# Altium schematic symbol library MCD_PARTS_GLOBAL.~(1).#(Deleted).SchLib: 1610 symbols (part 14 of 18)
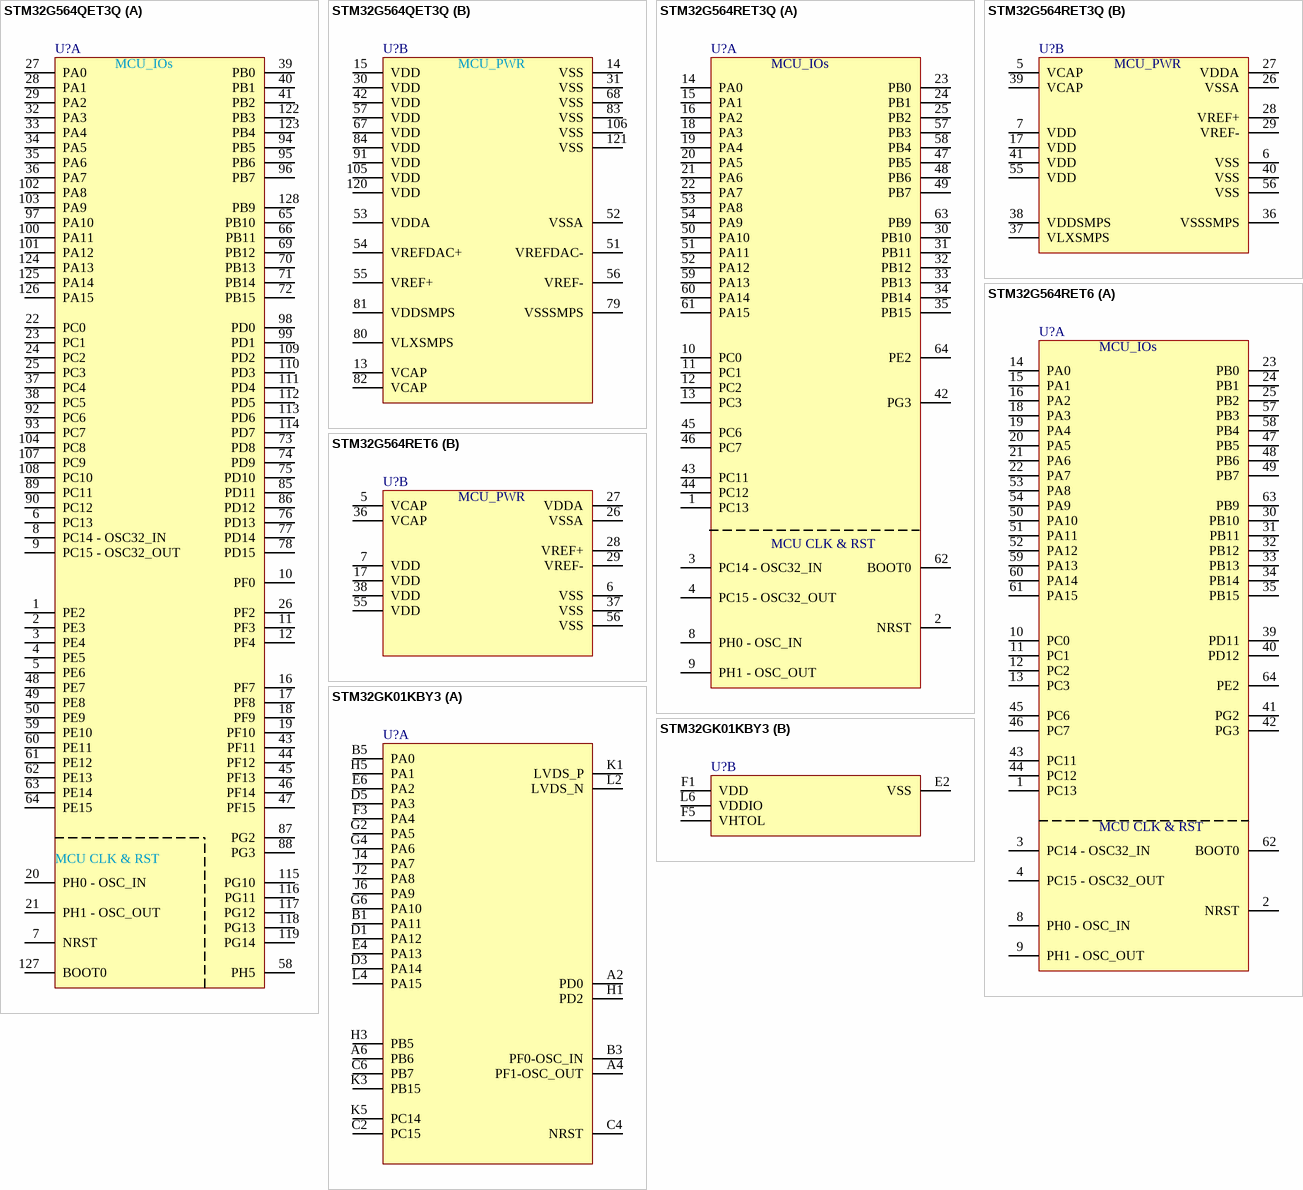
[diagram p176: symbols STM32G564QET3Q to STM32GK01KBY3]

## STM32G564QET3Q
designator U?
part A pins: 1 PE2, 2 PE3, 3 PE4, 4 PE5, 5 PE6, 6 PC13, 7 NRST, 8 PC14 - OSC32_IN, 9 PC15 - OSC32_OUT, 10 PF0, 11 PF3, 12 PF4, 16 PF7, 17 PF8, 18 PF9, 19 PF10, 20 PH0 - OSC_IN, 21 PH1 - OSC_OUT, 22 PC0, 23 PC1, 24 PC2, 25 PC3, 26 PF2, 27 PA0, 28 PA1, 29 PA2, 32 PA3, 33 PA4, 34 PA5, 35 PA6, 36 PA7, 37 PC4, 38 PC5, 39 PB0, 40 PB1, 41 PB2, 43 PF11, 44 PF12, 45 PF13, 46 PF14, 47 PF15, 48 PE7, 49 PE8, 50 PE9, 58 PH5, 59 PE10, 60 PE11, 61 PE12, 62 PE13, 63 PE14, 64 PE15, 65 PB10, 66 PB11, 69 PB12, 70 PB13, 71 PB14, 72 PB15, 73 PD8, 74 PD9, 75 PD10, 76 PD13, 77 PD14, 78 PD15, 85 PD11, 86 PD12, 87 PG2, 88 PG3, 89 PC11, 90 PC12, 92 PC6, 93 PC7, 94 PB5, 95 PB6, 96 PB7, 97 PA10, 98 PD0, 99 PD1, 100 PA11, 101 PA12, 102 PA8, 103 PA9, 104 PC8, 107 PC9, 108 PC10, 109 PD2, 110 PD3, 111 PD4, 112 PD5, 113 PD6, 114 PD7, 115 PG10, 116 PG11, 117 PG12, 118 PG13, 119 PG14, 122 PB3, 123 PB4, 124 PA13, 125 PA14, 126 PA15, 127 BOOT0, 128 PB9
part B pins: 13 VCAP, 14 VSS, 15 VDD, 30 VDD, 31 VSS, 42 VDD, 51 VREFDAC-, 52 VSSA, 53 VDDA, 54 VREFDAC+, 55 VREF+, 56 VREF-, 57 VDD, 67 VDD, 68 VSS, 79 VSSSMPS, 80 VLXSMPS, 81 VDDSMPS, 82 VCAP, 83 VSS, 84 VDD, 91 VDD, 105 VDD, 106 VSS, 120 VDD, 121 VSS

## STM32G564RET3Q
designator U?
part A pins: 1 PC13, 2 NRST, 3 PC14 - OSC32_IN, 4 PC15 - OSC32_OUT, 8 PH0 - OSC_IN, 9 PH1 - OSC_OUT, 10 PC0, 11 PC1, 12 PC2, 13 PC3, 14 PA0, 15 PA1, 16 PA2, 18 PA3, 19 PA4, 20 PA5, 21 PA6, 22 PA7, 23 PB0, 24 PB1, 25 PB2, 30 PB10, 31 PB11, 32 PB12, 33 PB13, 34 PB14, 35 PB15, 42 PG3, 43 PC11, 44 PC12, 45 PC6, 46 PC7, 47 PB5, 48 PB6, 49 PB7, 50 PA10, 51 PA11, 52 PA12, 53 PA8, 54 PA9, 57 PB3, 58 PB4, 59 PA13, 60 PA14, 61 PA15, 62 BOOT0, 63 PB9, 64 PE2
part B pins: 5 VCAP, 6 VSS, 7 VDD, 17 VDD, 26 VSSA, 27 VDDA, 28 VREF+, 29 VREF-, 36 VSSSMPS, 37 VLXSMPS, 38 VDDSMPS, 39 VCAP, 40 VSS, 41 VDD, 55 VDD, 56 VSS

## STM32G564RET6
designator U?
part A pins: 1 PC13, 2 NRST, 3 PC14 - OSC32_IN, 4 PC15 - OSC32_OUT, 8 PH0 - OSC_IN, 9 PH1 - OSC_OUT, 10 PC0, 11 PC1, 12 PC2, 13 PC3, 14 PA0, 15 PA1, 16 PA2, 18 PA3, 19 PA4, 20 PA5, 21 PA6, 22 PA7, 23 PB0, 24 PB1, 25 PB2, 30 PB10, 31 PB11, 32 PB12, 33 PB13, 34 PB14, 35 PB15, 39 PD11, 40 PD12, 41 PG2, 42 PG3, 43 PC11, 44 PC12, 45 PC6, 46 PC7, 47 PB5, 48 PB6, 49 PB7, 50 PA10, 51 PA11, 52 PA12, 53 PA8, 54 PA9, 57 PB3, 58 PB4, 59 PA13, 60 PA14, 61 PA15, 62 BOOT0, 63 PB9, 64 PE2
part B pins: 5 VCAP, 6 VSS, 7 VDD, 17 VDD, 26 VSSA, 27 VDDA, 28 VREF+, 29 VREF-, 36 VCAP, 37 VSS, 38 VDD, 55 VDD, 56 VSS

## STM32GK01KBY3
designator U?
part A pins: A2 PD0, A4 PF1-OSC_OUT, A6 PB6, B1 PA11, B3 PF0-OSC_IN, B5 PA0, C2 PC15, C4 NRST, C6 PB7, D1 PA12, D3 PA14, D5 PA3, E4 PA13, E6 PA2, F3 PA4, G2 PA5, G4 PA6, G6 PA10, H1 PD2, H3 PB5, H5 PA1, J2 PA8, J4 PA7, J6 PA9, K1 LVDS_P, K3 PB15, K5 PC14, L2 LVDS_N, L4 PA15
part B pins: E2 VSS, F1 VDD (power), F5 VHTOL (power), L6 VDDIO (power)

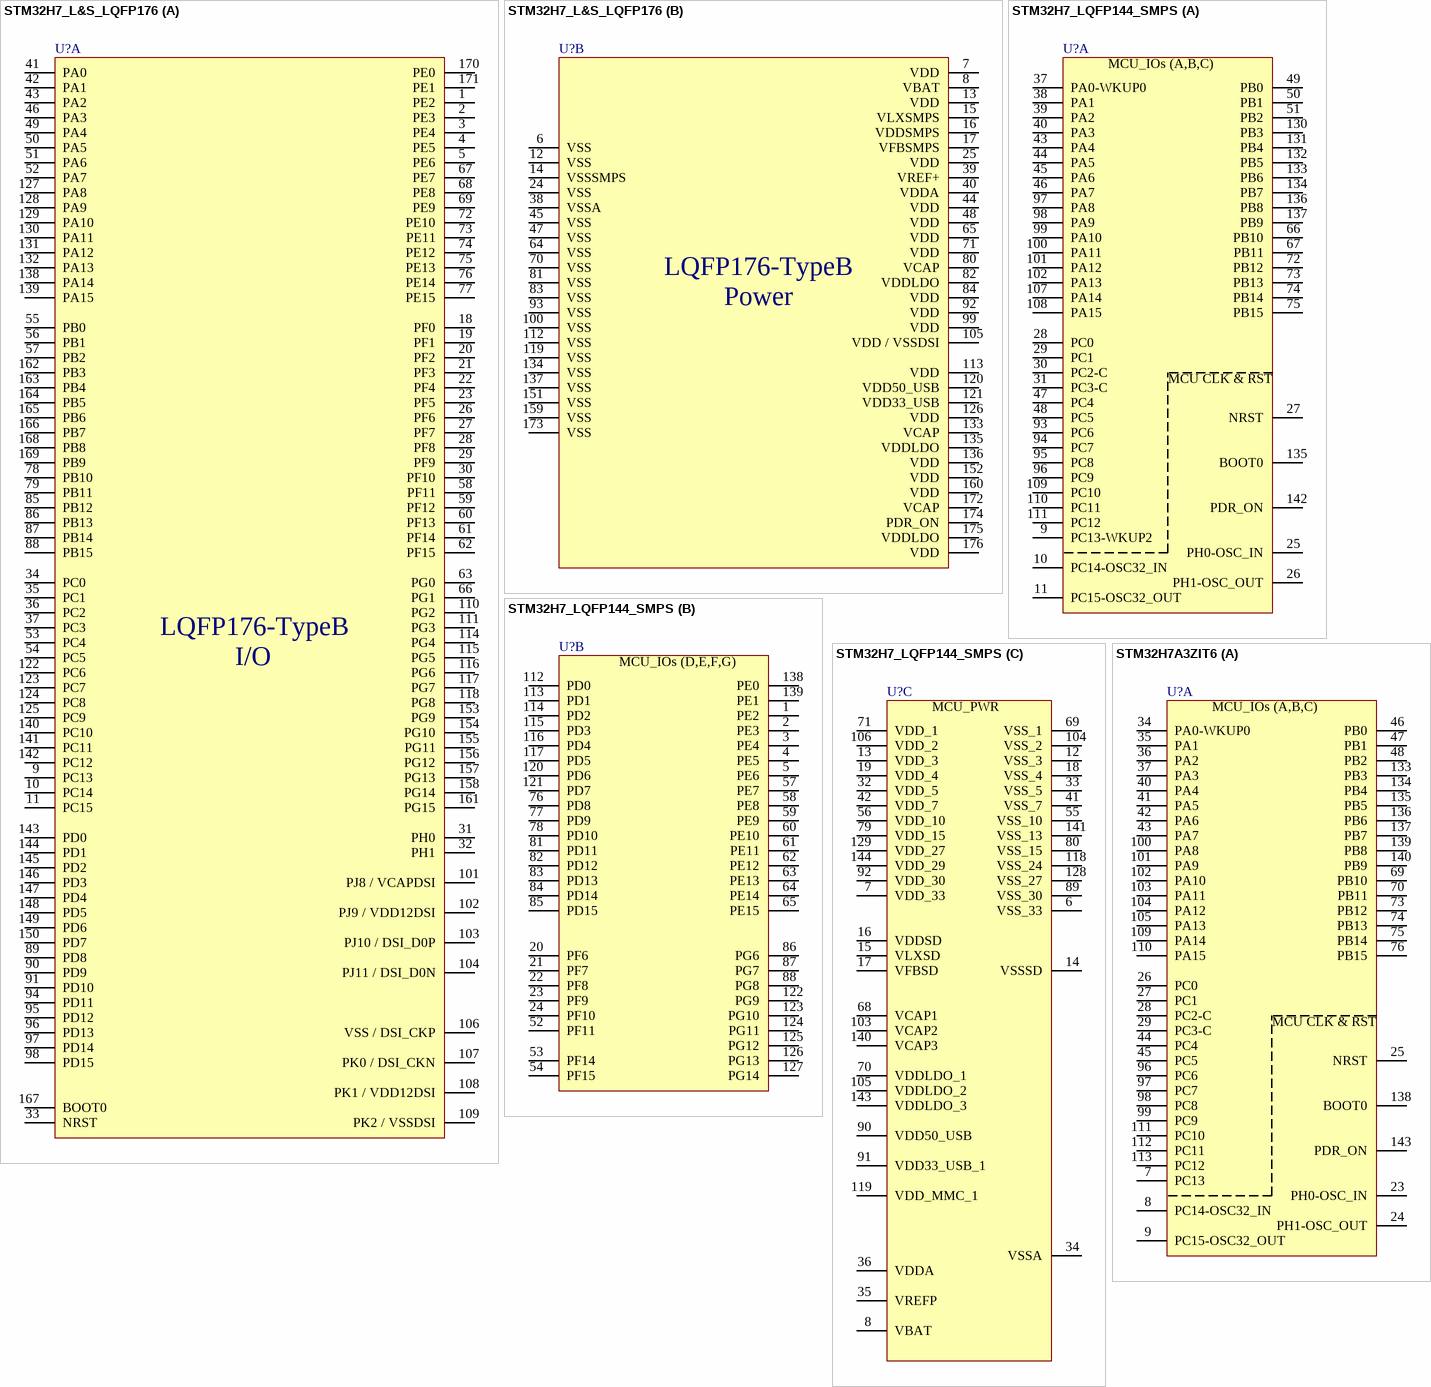
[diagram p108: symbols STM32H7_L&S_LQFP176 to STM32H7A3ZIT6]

## STM32H7_L&S_LQFP176
designator U?
part A pins: 1 PE2, 2 PE3, 3 PE4, 4 PE5, 5 PE6, 9 PC13, 10 PC14, 11 PC15, 18 PF0, 19 PF1, 20 PF2, 21 PF3, 22 PF4, 23 PF5, 26 PF6, 27 PF7, 28 PF8, 29 PF9, 30 PF10, 31 PH0, 32 PH1, 33 NRST, 34 PC0, 35 PC1, 36 PC2, 37 PC3, 41 PA0, 42 PA1, 43 PA2, 46 PA3, 49 PA4, 50 PA5, 51 PA6, 52 PA7, 53 PC4, 54 PC5, 55 PB0, 56 PB1, 57 PB2, 58 PF11, 59 PF12, 60 PF13, 61 PF14, 62 PF15, 63 PG0, 66 PG1, 67 PE7, 68 PE8, 69 PE9, 72 PE10, 73 PE11, 74 PE12, 75 PE13, 76 PE14, 77 PE15, 78 PB10, 79 PB11, 85 PB12, 86 PB13, 87 PB14, 88 PB15, 89 PD8, 90 PD9, 91 PD10, 94 PD11, 95 PD12, 96 PD13, 97 PD14, 98 PD15, 101 PJ8 / VCAPDSI, 102 PJ9 / VDD12DSI, 103 PJ10 / DSI_D0P, 104 PJ11 / DSI_D0N, 106 VSS / DSI_CKP, 107 PK0 / DSI_CKN, 108 PK1 / VDD12DSI, 109 PK2 / VSSDSI, 110 PG2, 111 PG3, 114 PG4, 115 PG5, 116 PG6, 117 PG7, 118 PG8, 122 PC6, 123 PC7, 124 PC8, 125 PC9, 127 PA8, 128 PA9, 129 PA10, 130 PA11, 131 PA12, 132 PA13, 138 PA14, 139 PA15, 140 PC10, 141 PC11, 142 PC12, 143 PD0, 144 PD1, 145 PD2, 146 PD3, 147 PD4, 148 PD5, 149 PD6, 150 PD7, 153 PG9, 154 PG10, 155 PG11, 156 PG12, 157 PG13, 158 PG14, 161 PG15, 162 PB3, 163 PB4, 164 PB5, 165 PB6, 166 PB7, 167 BOOT0, 168 PB8, 169 PB9, 170 PE0, 171 PE1
part B pins: 6 VSS, 7 VDD, 8 VBAT, 12 VSS, 13 VDD, 14 VSSSMPS, 15 VLXSMPS, 16 VDDSMPS, 17 VFBSMPS, 24 VSS, 25 VDD, 38 VSSA, 39 VREF+, 40 VDDA, 44 VDD, 45 VSS, 47 VSS, 48 VDD, 64 VSS, 65 VDD, 70 VSS, 71 VDD, 80 VCAP, 81 VSS, 82 VDDLDO, 83 VSS, 84 VDD, 92 VDD, 93 VSS, 99 VDD, 100 VSS, 105 VDD / VSSDSI, 112 VSS, 113 VDD, 119 VSS, 120 VDD50_USB, 121 VDD33_USB, 126 VDD, 133 VCAP, 134 VSS, 135 VDDLDO, 136 VDD, 137 VSS, 151 VSS, 152 VDD, 159 VSS, 160 VDD, 172 VCAP, 173 VSS, 174 PDR_ON, 175 VDDLDO, 176 VDD

## STM32H7_LQFP144_SMPS
designator U?
part A pins: 9 PC13-WKUP2, 10 PC14-OSC32_IN, 11 PC15-OSC32_OUT, 25 PH0-OSC_IN, 26 PH1-OSC_OUT, 27 NRST, 28 PC0, 29 PC1, 30 PC2-C, 31 PC3-C, 37 PA0-WKUP0, 38 PA1, 39 PA2, 40 PA3, 43 PA4, 44 PA5, 45 PA6, 46 PA7, 47 PC4, 48 PC5, 49 PB0, 50 PB1, 51 PB2, 66 PB10, 67 PB11, 72 PB12, 73 PB13, 74 PB14, 75 PB15, 93 PC6, 94 PC7, 95 PC8, 96 PC9, 97 PA8, 98 PA9, 99 PA10, 100 PA11, 101 PA12, 102 PA13, 107 PA14, 108 PA15, 109 PC10, 110 PC11, 111 PC12, 130 PB3, 131 PB4, 132 PB5, 133 PB6, 134 PB7, 135 BOOT0, 136 PB8, 137 PB9, 142 PDR_ON
part B pins: 1 PE2, 2 PE3, 3 PE4, 4 PE5, 5 PE6, 20 PF6, 21 PF7, 22 PF8, 23 PF9, 24 PF10, 52 PF11, 53 PF14, 54 PF15, 57 PE7, 58 PE8, 59 PE9, 60 PE10, 61 PE11, 62 PE12, 63 PE13, 64 PE14, 65 PE15, 76 PD8, 77 PD9, 78 PD10, 81 PD11, 82 PD12, 83 PD13, 84 PD14, 85 PD15, 86 PG6, 87 PG7, 88 PG8, 112 PD0, 113 PD1, 114 PD2, 115 PD3, 116 PD4, 117 PD5, 120 PD6, 121 PD7, 122 PG9, 123 PG10, 124 PG11, 125 PG12, 126 PG13, 127 PG14, 138 PE0, 139 PE1
part C pins: 6 VSS_33, 7 VDD_33, 8 VBAT, 12 VSS_3, 13 VDD_3, 14 VSSSD, 15 VLXSD, 16 VDDSD, 17 VFBSD, 18 VSS_4, 19 VDD_4, 32 VDD_5, 33 VSS_5, 34 VSSA, 35 VREFP, 36 VDDA, 41 VSS_7, 42 VDD_7, 55 VSS_10, 56 VDD_10, 68 VCAP1, 69 VSS_1, 70 VDDLDO_1, 71 VDD_1, 79 VDD_15, 80 VSS_15, 89 VSS_30, 90 VDD50_USB, 91 VDD33_USB_1, 92 VDD_30, 103 VCAP2, 104 VSS_2, 105 VDDLDO_2, 106 VDD_2, 118 VSS_24, 119 VDD_MMC_1, 128 VSS_27, 129 VDD_27, 140 VCAP3, 141 VSS_13, 143 VDDLDO_3, 144 VDD_29

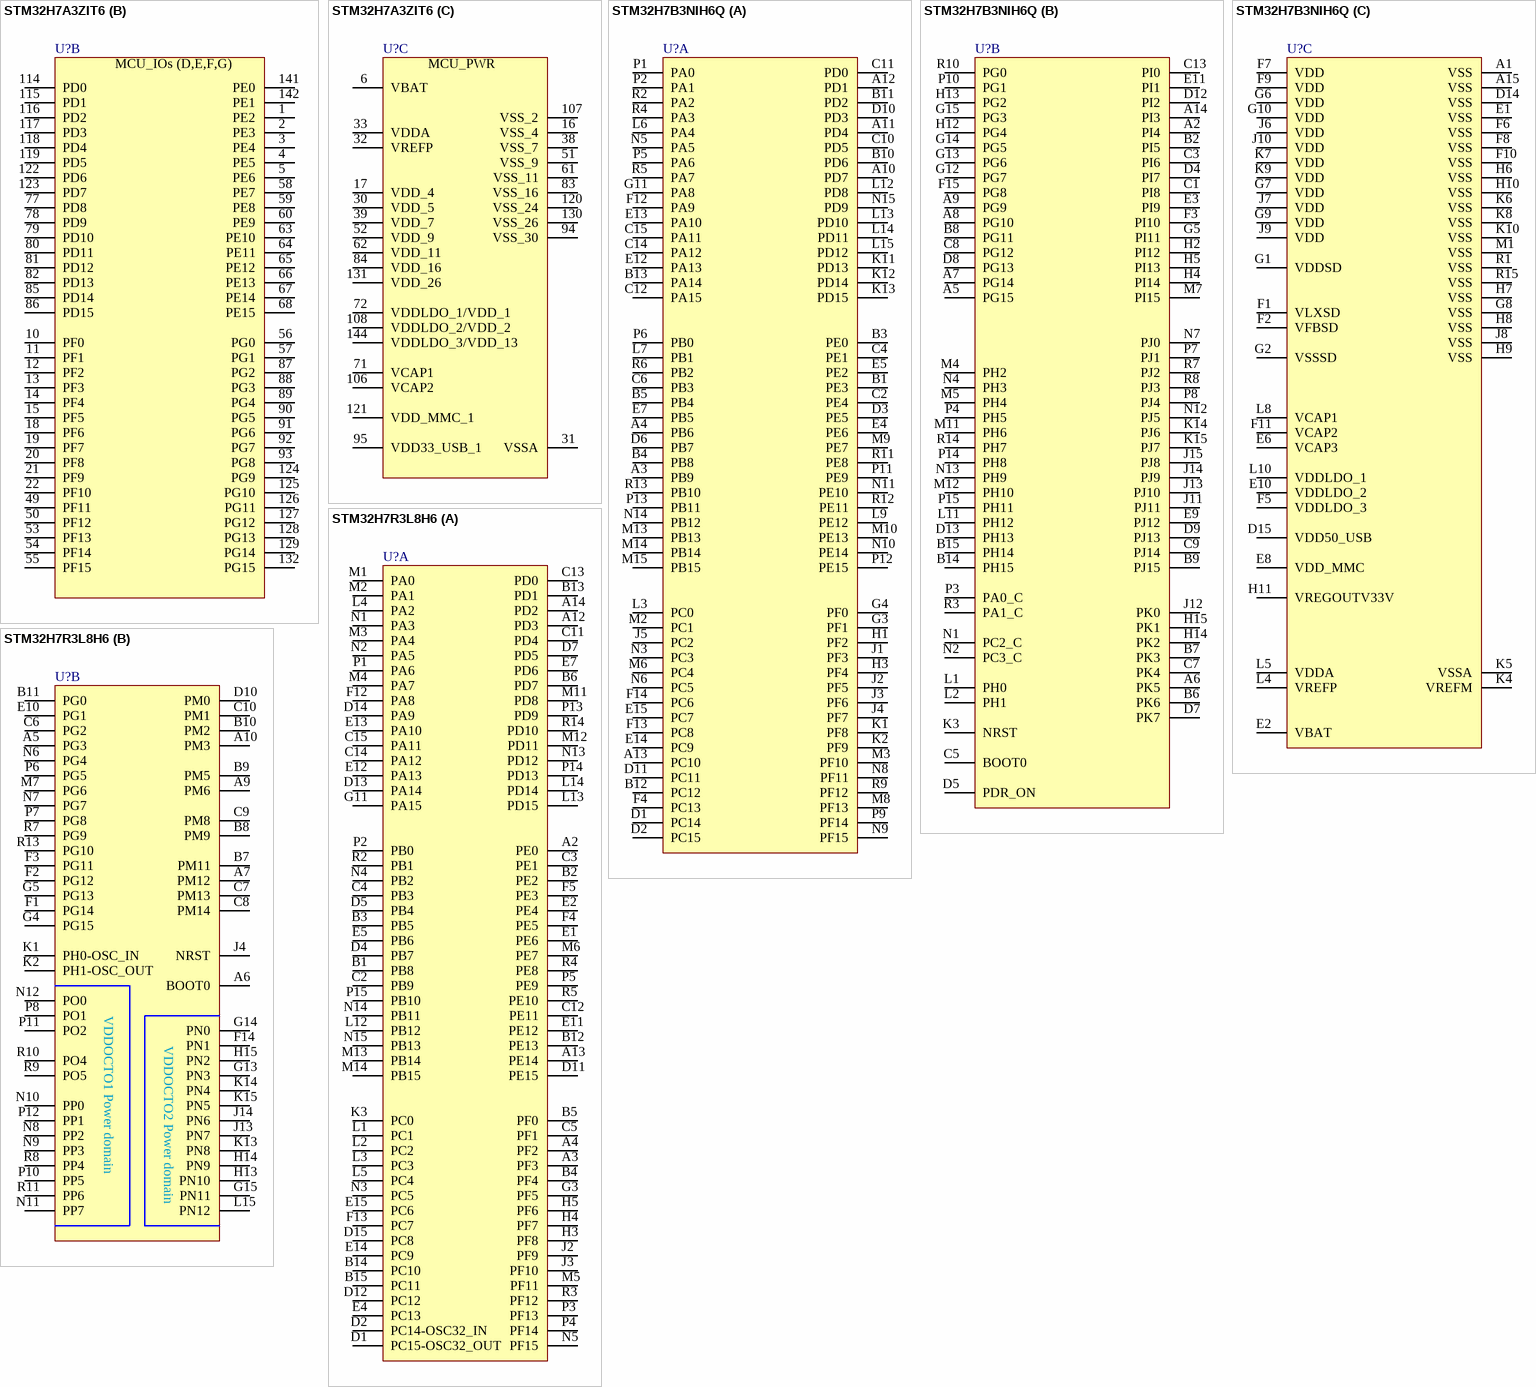
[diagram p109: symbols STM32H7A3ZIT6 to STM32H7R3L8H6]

## STM32H7A3ZIT6
designator U?
part A pins: 7 PC13, 8 PC14-OSC32_IN, 9 PC15-OSC32_OUT, 23 PH0-OSC_IN, 24 PH1-OSC_OUT, 25 NRST, 26 PC0, 27 PC1, 28 PC2-C, 29 PC3-C, 34 PA0-WKUP0, 35 PA1, 36 PA2, 37 PA3, 40 PA4, 41 PA5, 42 PA6, 43 PA7, 44 PC4, 45 PC5, 46 PB0, 47 PB1, 48 PB2, 69 PB10, 70 PB11, 73 PB12, 74 PB13, 75 PB14, 76 PB15, 96 PC6, 97 PC7, 98 PC8, 99 PC9, 100 PA8, 101 PA9, 102 PA10, 103 PA11, 104 PA12, 105 PA13, 109 PA14, 110 PA15, 111 PC10, 112 PC11, 113 PC12, 133 PB3, 134 PB4, 135 PB5, 136 PB6, 137 PB7, 138 BOOT0, 139 PB8, 140 PB9, 143 PDR_ON
part B pins: 1 PE2, 2 PE3, 3 PE4, 4 PE5, 5 PE6, 10 PF0, 11 PF1, 12 PF2, 13 PF3, 14 PF4, 15 PF5, 18 PF6, 19 PF7, 20 PF8, 21 PF9, 22 PF10, 49 PF11, 50 PF12, 53 PF13, 54 PF14, 55 PF15, 56 PG0, 57 PG1, 58 PE7, 59 PE8, 60 PE9, 63 PE10, 64 PE11, 65 PE12, 66 PE13, 67 PE14, 68 PE15, 77 PD8, 78 PD9, 79 PD10, 80 PD11, 81 PD12, 82 PD13, 85 PD14, 86 PD15, 87 PG2, 88 PG3, 89 PG4, 90 PG5, 91 PG6, 92 PG7, 93 PG8, 114 PD0, 115 PD1, 116 PD2, 117 PD3, 118 PD4, 119 PD5, 122 PD6, 123 PD7, 124 PG9, 125 PG10, 126 PG11, 127 PG12, 128 PG13, 129 PG14, 132 PG15, 141 PE0, 142 PE1
part C pins: 6 VBAT, 16 VSS_4, 17 VDD_4, 30 VDD_5, 31 VSSA, 32 VREFP, 33 VDDA, 38 VSS_7, 39 VDD_7, 51 VSS_9, 52 VDD_9, 61 VSS_11, 62 VDD_11, 71 VCAP1, 72 VDDLDO_1/VDD_1, 83 VSS_16, 84 VDD_16, 94 VSS_30, 95 VDD33_USB_1, 106 VCAP2, 107 VSS_2, 108 VDDLDO_2/VDD_2, 120 VSS_24, 121 VDD_MMC_1, 130 VSS_26, 131 VDD_26, 144 VDDLDO_3/VDD_13

## STM32H7B3NIH6Q
designator U?
part A pins: A3 PB9, A4 PB6, A10 PD7, A11 PD4, A12 PD1, A13 PC10, B1 PE3, B3 PE0, B4 PB8, B5 PB4, B10 PD6, B11 PD2, B12 PC12, B13 PA14, C2 PE4, C4 PE1, C6 PB3, C10 PD5, C11 PD0, C12 PA15, C14 PA12, C15 PA11, D1 PC14, D2 PC15, D3 PE5, D6 PB7, D10 PD3, D11 PC11, E4 PE6, E5 PE2, E7 PB5, E12 PA13, E13 PA10, E14 PC9, E15 PC7, F4 PC13, F12 PA9, F13 PC8, F14 PC6, G3 PF1, G4 PF0, G11 PA8, H1 PF2, H3 PF4, J1 PF3, J2 PF5, J3 PF6, J4 PF7, J5 PC2, K1 PF8, K2 PF9, K11 PD13, K12 PD14, K13 PD15, L3 PC0, L6 PA4, L7 PB1, L9 PE12, L12 PD8, L13 PD10, L14 PD11, L15 PD12, M2 PC1, M3 PF10, M6 PC4, M8 PF13, M9 PE7, M10 PE13, M13 PB13, M14 PB14, M15 PB15, N3 PC3, N5 PA5, N6 PC5, N8 PF11, N9 PF15, N10 PE14, N11 PE10, N14 PB12, N15 PD9, P1 PA0, P2 PA1, P5 PA6, P6 PB0, P9 PF14, P11 PE9, P12 PE15, P13 PB11, R2 PA2, R4 PA3, R5 PA7, R6 PB2, R9 PF12, R11 PE8, R12 PE11, R13 PB10
part B pins: A2 PI4, A5 PG15, A6 PK5, A7 PG14, A8 PG10, A9 PG9, A14 PI3, B2 PI5, B6 PK6, B7 PK3, B8 PG11, B9 PJ15, B14 PH15, B15 PH14, C1 PI8, C3 PI6, C5 BOOT0, C7 PK4, C8 PG12, C9 PJ14, C13 PI0, D4 PI7, D5 PDR_ON, D7 PK7, D8 PG13, D9 PJ13, D12 PI2, D13 PH13, E3 PI9, E9 PJ12, E11 PI1, F3 PI10, F15 PG8, G5 PI11, G12 PG7, G13 PG6, G14 PG5, G15 PG3, H2 PI12, H4 PI14, H5 PI13, H12 PG4, H13 PG2, H14 PK2, H15 PK1, J11 PJ11, J12 PK0, J13 PJ10, J14 PJ9, J15 PJ8, K3 NRST, K14 PJ6, K15 PJ7, L1 PH0, L2 PH1, L11 PH12, M4 PH2, M5 PH4, M7 PI15, M11 PH6, M12 PH10, N1 PC2_C, N2 PC3_C, N4 PH3, N7 PJ0, N12 PJ5, N13 PH9, P3 PA0_C, P4 PH5, P7 PJ1, P8 PJ4, P10 PG1, P14 PH8, P15 PH11, R3 PA1_C, R7 PJ2, R8 PJ3, R10 PG0, R14 PH7
part C pins: A1 VSS, A15 VSS, D14 VSS, D15 VDD50_USB, E1 VSS, E2 VBAT, E6 VCAP3, E8 VDD_MMC, E10 VDDLDO_2, F1 VLXSD, F2 VFBSD, F5 VDDLDO_3, F6 VSS, F7 VDD, F8 VSS, F9 VDD, F10 VSS, F11 VCAP2, G1 VDDSD, G2 VSSSD, G6 VDD, G7 VDD, G8 VSS, G9 VDD, G10 VDD, H6 VSS, H7 VSS, H8 VSS, H9 VSS, H10 VSS, H11 VREGOUTV33V, J6 VDD, J7 VDD, J8 VSS, J9 VDD, J10 VDD, K4 VREFM, K5 VSSA, K6 VSS, K7 VDD, K8 VSS, K9 VDD, K10 VSS, L4 VREFP, L5 VDDA, L8 VCAP1, L10 VDDLDO_1, M1 VSS, R1 VSS, R15 VSS

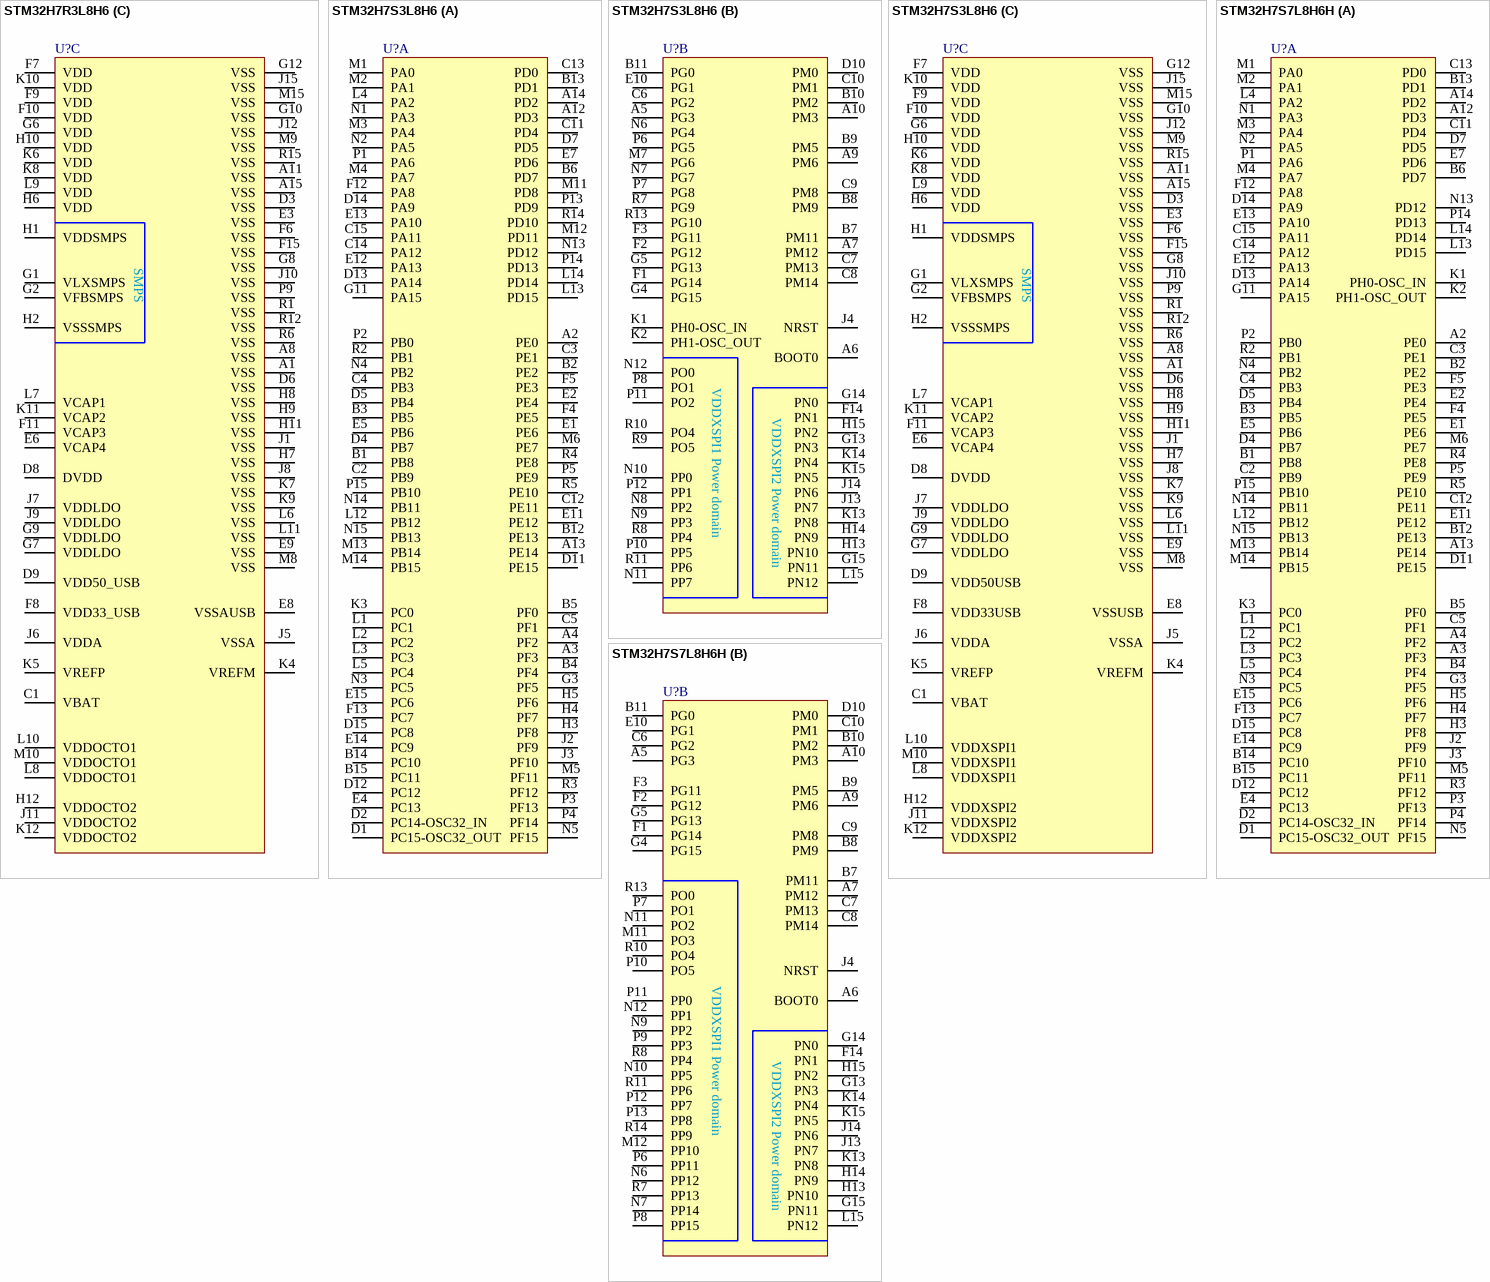
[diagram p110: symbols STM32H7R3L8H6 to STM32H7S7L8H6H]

## STM32H7R3L8H6
designator U?
part A pins: A2 PE0, A3 PF3, A4 PF2, A12 PD3, A13 PE14, A14 PD2, B1 PB8, B2 PE2, B3 PB5, B4 PF4, B5 PF0, B6 PD7, B12 PE13, B13 PD1, B14 PC10, B15 PC11, C2 PB9, C3 PE1, C4 PB3, C5 PF1, C11 PD4, C12 PE11, C13 PD0, C14 PA12, C15 PA11, D1 PC15-OSC32_OUT, D2 PC14-OSC32_IN, D4 PB7, D5 PB4, D7 PD5, D11 PE15, D12 PC12, D13 PA14, D14 PA9, D15 PC8, E1 PE6, E2 PE4, E4 PC13, E5 PB6, E7 PD6, E11 PE12, E12 PA13, E13 PA10, E14 PC9, E15 PC6, F4 PE5, F5 PE3, F12 PA8, F13 PC7, G3 PF5, G11 PA15, H3 PF8, H4 PF7, H5 PF6, J2 PF9, J3 PF10, K3 PC0, L1 PC1, L2 PC2, L3 PC3, L4 PA2, L5 PC4, L12 PB12, L13 PD15, L14 PD14, M1 PA0, M2 PA1, M3 PA4, M4 PA7, M5 PF11, M6 PE7, M11 PD8, M12 PD11, M13 PB14, M14 PB15, N1 PA3, N2 PA5, N3 PC5, N4 PB2, N5 PF15, N13 PD12, N14 PB11, N15 PB13, P1 PA6, P2 PB0, P3 PF13, P4 PF14, P5 PE9, P13 PD9, P14 PD13, P15 PB10, R2 PB1, R3 PF12, R4 PE8, R5 PE10, R14 PD10
part B pins: A5 PG3, A6 BOOT0, A7 PM12, A9 PM6, A10 PM3, B7 PM11, B8 PM9, B9 PM5, B10 PM2, B11 PG0, C6 PG2, C7 PM13, C8 PM14, C9 PM8, C10 PM1, D10 PM0, E10 PG1, F1 PG14, F2 PG12, F3 PG11, F14 PN1, G4 PG15, G5 PG13, G13 PN3, G14 PN0, G15 PN11, H13 PN10, H14 PN9, H15 PN2, J4 NRST, J13 PN7, J14 PN6, K1 PH0-OSC_IN, K2 PH1-OSC_OUT, K13 PN8, K14 PN4, K15 PN5, L15 PN12, M7 PG6, N6 PG4, N7 PG7, N8 PP2, N9 PP3, N10 PP0, N11 PP7, N12 PO0, P6 PG5, P7 PG8, P8 PO1, P10 PP5, P11 PO2, P12 PP1, R7 PG9, R8 PP4, R9 PO5, R10 PO4, R11 PP6, R13 PG10
part C pins: A1 VSS, A8 VSS, A11 VSS, A15 VSS, C1 VBAT, D3 VSS, D6 VSS, D8 DVDD, D9 VDD50_USB, E3 VSS, E6 VCAP4, E8 VSSAUSB, E9 VSS, F6 VSS, F7 VDD, F8 VDD33_USB, F9 VDD, F10 VDD, F11 VCAP3, F15 VSS, G1 VLXSMPS, G2 VFBSMPS, G6 VDD, G7 VDDLDO, G8 VSS, G9 VDDLDO, G10 VSS, G12 VSS, H1 VDDSMPS, H2 VSSSMPS, H6 VDD, H7 VSS, H8 VSS, H9 VSS, H10 VDD, H11 VSS, H12 VDDOCTO2, J1 VSS, J5 VSSA, J6 VDDA, J7 VDDLDO, J8 VSS, J9 VDDLDO, J10 VSS, J11 VDDOCTO2, J12 VSS, J15 VSS, K4 VREFM, K5 VREFP, K6 VDD, K7 VSS, K8 VDD, K9 VSS, K10 VDD, K11 VCAP2, K12 VDDOCTO2, L6 VSS, L7 VCAP1, L8 VDDOCTO1, L9 VDD, L10 VDDOCTO1, L11 VSS, M8 VSS, M9 VSS, M10 VDDOCTO1, M15 VSS, P9 VSS, R1 VSS, R6 VSS, R12 VSS, R15 VSS

## STM32H7S3L8H6
designator U?
part A pins: A2 PE0, A3 PF3, A4 PF2, A12 PD3, A13 PE14, A14 PD2, B1 PB8, B2 PE2, B3 PB5, B4 PF4, B5 PF0, B6 PD7, B12 PE13, B13 PD1, B14 PC10, B15 PC11, C2 PB9, C3 PE1, C4 PB3, C5 PF1, C11 PD4, C12 PE11, C13 PD0, C14 PA12, C15 PA11, D1 PC15-OSC32_OUT, D2 PC14-OSC32_IN, D4 PB7, D5 PB4, D7 PD5, D11 PE15, D12 PC12, D13 PA14, D14 PA9, D15 PC8, E1 PE6, E2 PE4, E4 PC13, E5 PB6, E7 PD6, E11 PE12, E12 PA13, E13 PA10, E14 PC9, E15 PC6, F4 PE5, F5 PE3, F12 PA8, F13 PC7, G3 PF5, G11 PA15, H3 PF8, H4 PF7, H5 PF6, J2 PF9, J3 PF10, K3 PC0, L1 PC1, L2 PC2, L3 PC3, L4 PA2, L5 PC4, L12 PB12, L13 PD15, L14 PD14, M1 PA0, M2 PA1, M3 PA4, M4 PA7, M5 PF11, M6 PE7, M11 PD8, M12 PD11, M13 PB14, M14 PB15, N1 PA3, N2 PA5, N3 PC5, N4 PB2, N5 PF15, N13 PD12, N14 PB11, N15 PB13, P1 PA6, P2 PB0, P3 PF13, P4 PF14, P5 PE9, P13 PD9, P14 PD13, P15 PB10, R2 PB1, R3 PF12, R4 PE8, R5 PE10, R14 PD10
part B pins: A5 PG3, A6 BOOT0, A7 PM12, A9 PM6, A10 PM3, B7 PM11, B8 PM9, B9 PM5, B10 PM2, B11 PG0, C6 PG2, C7 PM13, C8 PM14, C9 PM8, C10 PM1, D10 PM0, E10 PG1, F1 PG14, F2 PG12, F3 PG11, F14 PN1, G4 PG15, G5 PG13, G13 PN3, G14 PN0, G15 PN11, H13 PN10, H14 PN9, H15 PN2, J4 NRST, J13 PN7, J14 PN6, K1 PH0-OSC_IN, K2 PH1-OSC_OUT, K13 PN8, K14 PN4, K15 PN5, L15 PN12, M7 PG6, N6 PG4, N7 PG7, N8 PP2, N9 PP3, N10 PP0, N11 PP7, N12 PO0, P6 PG5, P7 PG8, P8 PO1, P10 PP5, P11 PO2, P12 PP1, R7 PG9, R8 PP4, R9 PO5, R10 PO4, R11 PP6, R13 PG10
part C pins: A1 VSS, A8 VSS, A11 VSS, A15 VSS, C1 VBAT, D3 VSS, D6 VSS, D8 DVDD, D9 VDD50USB, E3 VSS, E6 VCAP4, E8 VSSUSB, E9 VSS, F6 VSS, F7 VDD, F8 VDD33USB, F9 VDD, F10 VDD, F11 VCAP3, F15 VSS, G1 VLXSMPS, G2 VFBSMPS, G6 VDD, G7 VDDLDO, G8 VSS, G9 VDDLDO, G10 VSS, G12 VSS, H1 VDDSMPS, H2 VSSSMPS, H6 VDD, H7 VSS, H8 VSS, H9 VSS, H10 VDD, H11 VSS, H12 VDDXSPI2, J1 VSS, J5 VSSA, J6 VDDA, J7 VDDLDO, J8 VSS, J9 VDDLDO, J10 VSS, J11 VDDXSPI2, J12 VSS, J15 VSS, K4 VREFM, K5 VREFP, K6 VDD, K7 VSS, K8 VDD, K9 VSS, K10 VDD, K11 VCAP2, K12 VDDXSPI2, L6 VSS, L7 VCAP1, L8 VDDXSPI1, L9 VDD, L10 VDDXSPI1, L11 VSS, M8 VSS, M9 VSS, M10 VDDXSPI1, M15 VSS, P9 VSS, R1 VSS, R6 VSS, R12 VSS, R15 VSS

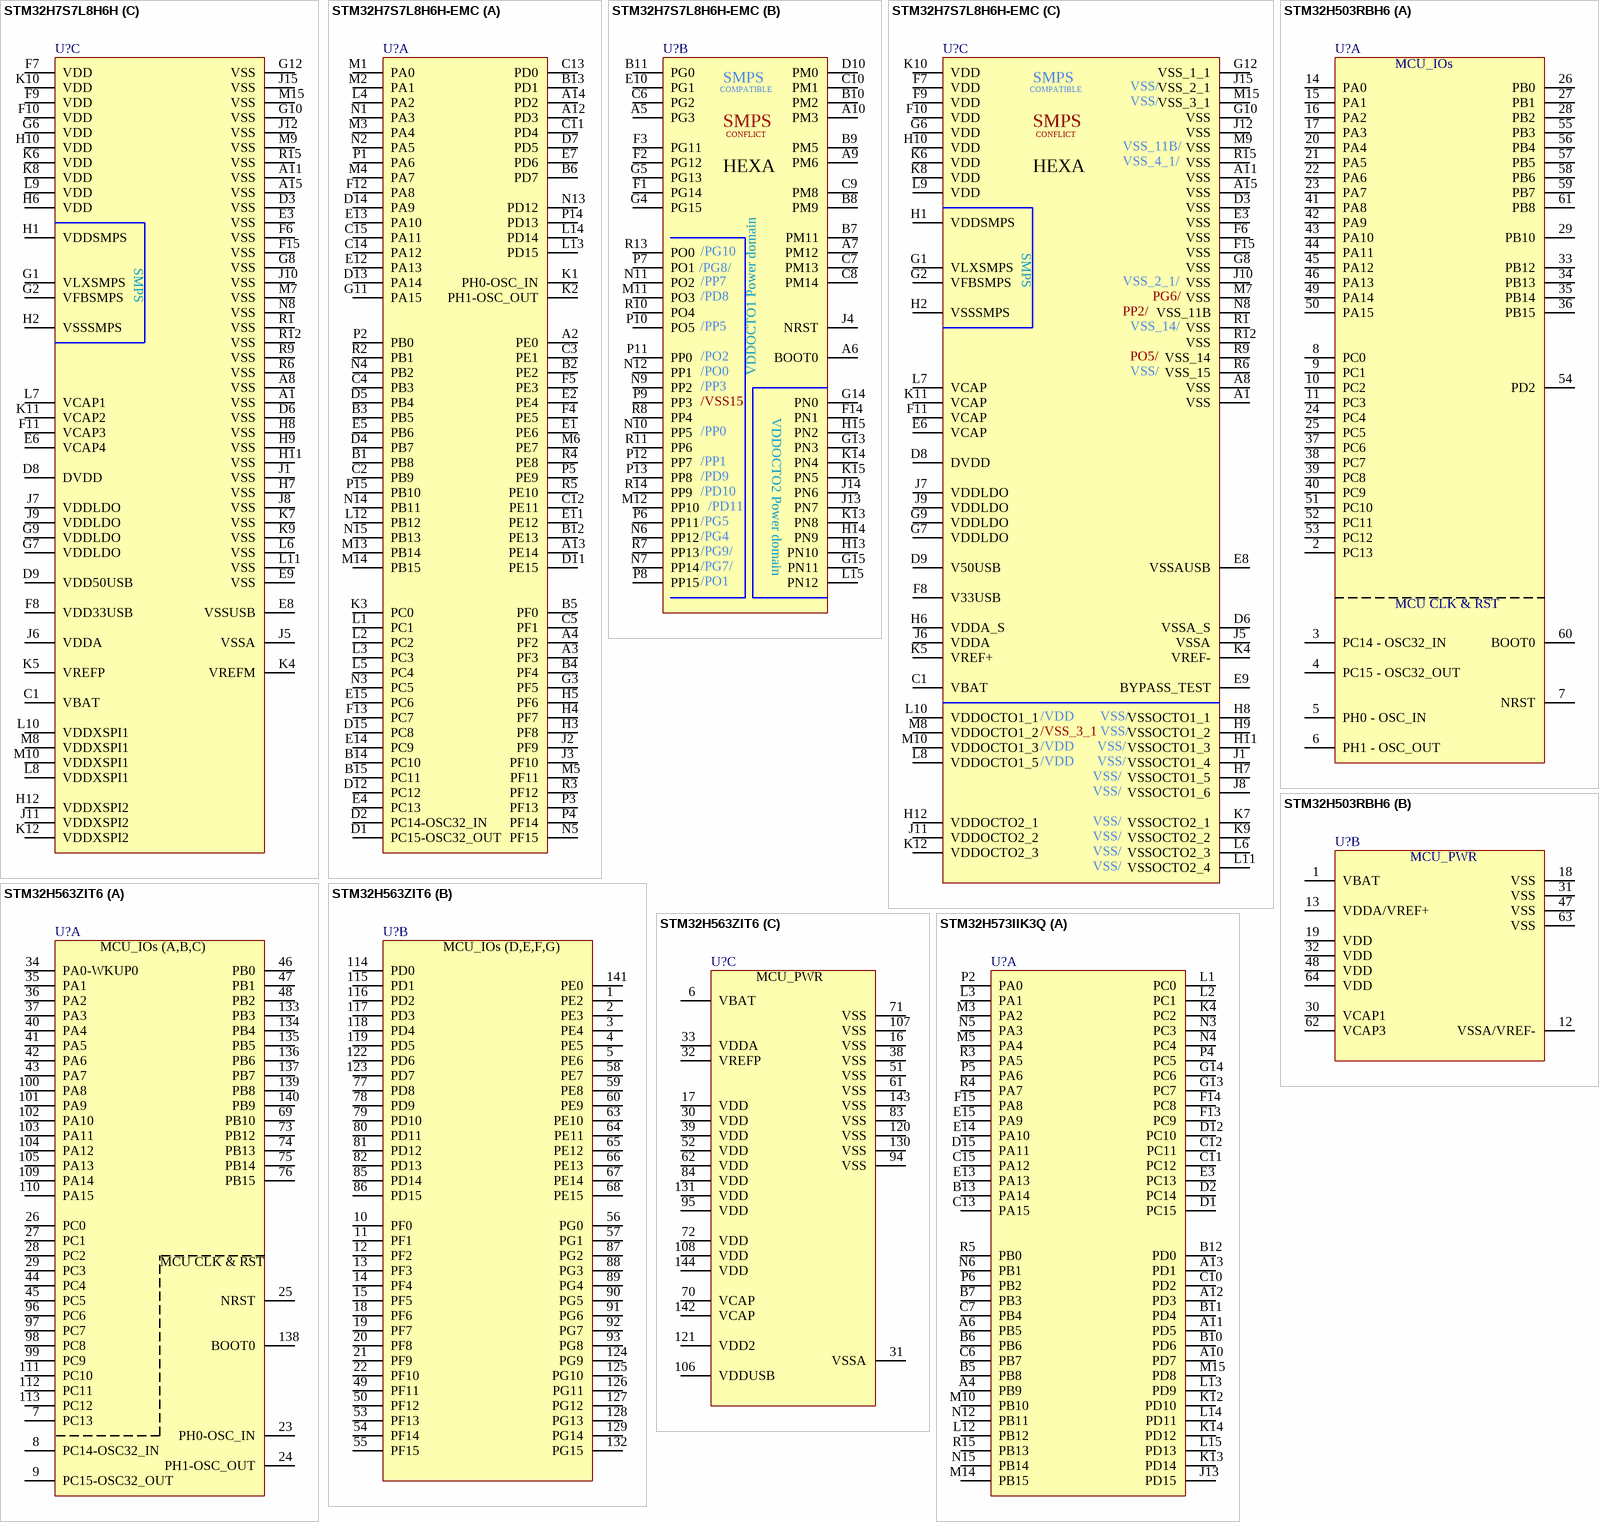
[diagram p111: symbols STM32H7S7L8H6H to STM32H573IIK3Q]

## STM32H7S7L8H6H
designator U?
part A pins: A2 PE0, A3 PF3, A4 PF2, A12 PD3, A13 PE14, A14 PD2, B1 PB8, B2 PE2, B3 PB5, B4 PF4, B5 PF0, B6 PD7, B12 PE13, B13 PD1, B14 PC10, B15 PC11, C2 PB9, C3 PE1, C4 PB3, C5 PF1, C11 PD4, C12 PE11, C13 PD0, C14 PA12, C15 PA11, D1 PC15-OSC32_OUT, D2 PC14-OSC32_IN, D4 PB7, D5 PB4, D7 PD5, D11 PE15, D12 PC12, D13 PA14, D14 PA9, D15 PC8, E1 PE6, E2 PE4, E4 PC13, E5 PB6, E7 PD6, E11 PE12, E12 PA13, E13 PA10, E14 PC9, E15 PC6, F4 PE5, F5 PE3, F12 PA8, F13 PC7, G3 PF5, G11 PA15, H3 PF8, H4 PF7, H5 PF6, J2 PF9, J3 PF10, K1 PH0-OSC_IN, K2 PH1-OSC_OUT, K3 PC0, L1 PC1, L2 PC2, L3 PC3, L4 PA2, L5 PC4, L12 PB12, L13 PD15, L14 PD14, M1 PA0, M2 PA1, M3 PA4, M4 PA7, M5 PF11, M6 PE7, M13 PB14, M14 PB15, N1 PA3, N2 PA5, N3 PC5, N4 PB2, N5 PF15, N13 PD12, N14 PB11, N15 PB13, P1 PA6, P2 PB0, P3 PF13, P4 PF14, P5 PE9, P14 PD13, P15 PB10, R2 PB1, R3 PF12, R4 PE8, R5 PE10
part B pins: A5 PG3, A6 BOOT0, A7 PM12, A9 PM6, A10 PM3, B7 PM11, B8 PM9, B9 PM5, B10 PM2, B11 PG0, C6 PG2, C7 PM13, C8 PM14, C9 PM8, C10 PM1, D10 PM0, E10 PG1, F1 PG14, F2 PG12, F3 PG11, F14 PN1, G4 PG15, G5 PG13, G13 PN3, G14 PN0, G15 PN11, H13 PN10, H14 PN9, H15 PN2, J4 NRST, J13 PN7, J14 PN6, K13 PN8, K14 PN4, K15 PN5, L15 PN12, M11 PO3, M12 PP10, N6 PP12, N7 PP14, N9 PP2, N10 PP5, N11 PO2, N12 PP1, P6 PP11, P7 PO1, P8 PP15, P9 PP3, P10 PO5, P11 PP0, P12 PP7, P13 PP8, R7 PP13, R8 PP4, R10 PO4, R11 PP6, R13 PO0, R14 PP9
part C pins: A1 VSS, A8 VSS, A11 VSS, A15 VSS, C1 VBAT, D3 VSS, D6 VSS, D8 DVDD, D9 VDD50USB, E3 VSS, E6 VCAP4, E8 VSSUSB, E9 VSS, F6 VSS, F7 VDD, F8 VDD33USB, F9 VDD, F10 VDD, F11 VCAP3, F15 VSS, G1 VLXSMPS, G2 VFBSMPS, G6 VDD, G7 VDDLDO, G8 VSS, G9 VDDLDO, G10 VSS, G12 VSS, H1 VDDSMPS, H2 VSSSMPS, H6 VDD, H7 VSS, H8 VSS, H9 VSS, H10 VDD, H11 VSS, H12 VDDXSPI2, J1 VSS, J5 VSSA, J6 VDDA, J7 VDDLDO, J8 VSS, J9 VDDLDO, J10 VSS, J11 VDDXSPI2, J12 VSS, J15 VSS, K4 VREFM, K5 VREFP, K6 VDD, K7 VSS, K8 VDD, K9 VSS, K10 VDD, K11 VCAP2, K12 VDDXSPI2, L6 VSS, L7 VCAP1, L8 VDDXSPI1, L9 VDD, L10 VDDXSPI1, L11 VSS, M7 VSS, M8 VDDXSPI1, M9 VSS, M10 VDDXSPI1, M15 VSS, N8 VSS, R1 VSS, R6 VSS, R9 VSS, R12 VSS, R15 VSS

## STM32H7S7L8H6H-EMC
designator U?
part A pins: A2 PE0, A3 PF3, A4 PF2, A12 PD3, A13 PE14, A14 PD2, B1 PB8, B2 PE2, B3 PB5, B4 PF4, B5 PF0, B6 PD7, B12 PE13, B13 PD1, B14 PC10, B15 PC11, C2 PB9, C3 PE1, C4 PB3, C5 PF1, C11 PD4, C12 PE11, C13 PD0, C14 PA12, C15 PA11, D1 PC15-OSC32_OUT, D2 PC14-OSC32_IN, D4 PB7, D5 PB4, D7 PD5, D11 PE15, D12 PC12, D13 PA14, D14 PA9, D15 PC8, E1 PE6, E2 PE4, E4 PC13, E5 PB6, E7 PD6, E11 PE12, E12 PA13, E13 PA10, E14 PC9, E15 PC6, F4 PE5, F5 PE3, F12 PA8, F13 PC7, G3 PF5, G11 PA15, H3 PF8, H4 PF7, H5 PF6, J2 PF9, J3 PF10, K1 PH0-OSC_IN, K2 PH1-OSC_OUT, K3 PC0, L1 PC1, L2 PC2, L3 PC3, L4 PA2, L5 PC4, L12 PB12, L13 PD15, L14 PD14, M1 PA0, M2 PA1, M3 PA4, M4 PA7, M5 PF11, M6 PE7, M13 PB14, M14 PB15, N1 PA3, N2 PA5, N3 PC5, N4 PB2, N5 PF15, N13 PD12, N14 PB11, N15 PB13, P1 PA6, P2 PB0, P3 PF13, P4 PF14, P5 PE9, P14 PD13, P15 PB10, R2 PB1, R3 PF12, R4 PE8, R5 PE10
part B pins: A5 PG3, A6 BOOT0, A7 PM12, A9 PM6, A10 PM3, B7 PM11, B8 PM9, B9 PM5, B10 PM2, B11 PG0, C6 PG2, C7 PM13, C8 PM14, C9 PM8, C10 PM1, D10 PM0, E10 PG1, F1 PG14, F2 PG12, F3 PG11, F14 PN1, G4 PG15, G5 PG13, G13 PN3, G14 PN0, G15 PN11, H13 PN10, H14 PN9, H15 PN2, J4 NRST, J13 PN7, J14 PN6, K13 PN8, K14 PN4, K15 PN5, L15 PN12, M11 PO3, M12 PP10, N6 PP12, N7 PP14, N9 PP2, N10 PP5, N11 PO2, N12 PP1, P6 PP11, P7 PO1, P8 PP15, P9 PP3, P10 PO5, P11 PP0, P12 PP7, P13 PP8, R7 PP13, R8 PP4, R10 PO4, R11 PP6, R13 PO0, R14 PP9
part C pins: A1 VSS, A8 VSS, A11 VSS, A15 VSS, C1 VBAT, D3 VSS, D6 VSSA_S, D8 DVDD, D9 V50USB, E3 VSS, E6 VCAP, E8 VSSAUSB, E9 BYPASS_TEST, F6 VSS, F7 VDD, F8 V33USB, F9 VDD, F10 VDD, F11 VCAP, F15 VSS, G1 VLXSMPS, G2 VFBSMPS, G6 VDD, G7 VDDLDO, G8 VSS, G9 VDDLDO, G10 VSS, G12 VSS_1_1, H1 VDDSMPS, H2 VSSSMPS, H6 VDDA_S, H7 VSSOCTO1_5, H8 VSSOCTO1_1, H9 VSSOCTO1_2, H10 VDD, H11 VSSOCTO1_3, H12 VDDOCTO2_1, J1 VSSOCTO1_4, J5 VSSA, J6 VDDA, J7 VDDLDO, J8 VSSOCTO1_6, J9 VDDLDO, J10 VSS, J11 VDDOCTO2_2, J12 VSS, J15 VSS_2_1, K4 VREF-, K5 VREF+, K6 VDD, K7 VSSOCTO2_1, K8 VDD, K9 VSSOCTO2_2, K10 VDD, K11 VCAP, K12 VDDOCTO2_3, L6 VSSOCTO2_3, L7 VCAP, L8 VDDOCTO1_5, L9 VDD, L10 VDDOCTO1_1, L11 VSSOCTO2_4, M7 VSS, M8 VDDOCTO1_2, M9 VSS, M10 VDDOCTO1_3, M15 VSS_3_1, N8 VSS_11B, R1 VSS, R6 VSS_15, R9 VSS_14, R12 VSS, R15 VSS

## STM32H503RBH6
designator U?
part A pins: 2 PC13, 3 PC14 - OSC32_IN, 4 PC15 - OSC32_OUT, 5 PH0 - OSC_IN, 6 PH1 - OSC_OUT, 7 NRST, 8 PC0, 9 PC1, 10 PC2, 11 PC3, 14 PA0, 15 PA1, 16 PA2, 17 PA3, 20 PA4, 21 PA5, 22 PA6, 23 PA7, 24 PC4, 25 PC5, 26 PB0, 27 PB1, 28 PB2, 29 PB10, 33 PB12, 34 PB13, 35 PB14, 36 PB15, 37 PC6, 38 PC7, 39 PC8, 40 PC9, 41 PA8, 42 PA9, 43 PA10, 44 PA11, 45 PA12, 46 PA13, 49 PA14, 50 PA15, 51 PC10, 52 PC11, 53 PC12, 54 PD2, 55 PB3, 56 PB4, 57 PB5, 58 PB6, 59 PB7, 60 BOOT0, 61 PB8
part B pins: 1 VBAT, 12 VSSA/VREF-, 13 VDDA/VREF+, 18 VSS, 19 VDD, 30 VCAP1, 31 VSS, 32 VDD, 47 VSS, 48 VDD, 62 VCAP3, 63 VSS, 64 VDD

## STM32H563ZIT6
designator U?
part A pins: 7 PC13, 8 PC14-OSC32_IN, 9 PC15-OSC32_OUT, 23 PH0-OSC_IN, 24 PH1-OSC_OUT, 25 NRST, 26 PC0, 27 PC1, 28 PC2, 29 PC3, 34 PA0-WKUP0, 35 PA1, 36 PA2, 37 PA3, 40 PA4, 41 PA5, 42 PA6, 43 PA7, 44 PC4, 45 PC5, 46 PB0, 47 PB1, 48 PB2, 69 PB10, 73 PB12, 74 PB13, 75 PB14, 76 PB15, 96 PC6, 97 PC7, 98 PC8, 99 PC9, 100 PA8, 101 PA9, 102 PA10, 103 PA11, 104 PA12, 105 PA13, 109 PA14, 110 PA15, 111 PC10, 112 PC11, 113 PC12, 133 PB3, 134 PB4, 135 PB5, 136 PB6, 137 PB7, 138 BOOT0, 139 PB8, 140 PB9
part B pins: 1 PE2, 2 PE3, 3 PE4, 4 PE5, 5 PE6, 10 PF0, 11 PF1, 12 PF2, 13 PF3, 14 PF4, 15 PF5, 18 PF6, 19 PF7, 20 PF8, 21 PF9, 22 PF10, 49 PF11, 50 PF12, 53 PF13, 54 PF14, 55 PF15, 56 PG0, 57 PG1, 58 PE7, 59 PE8, 60 PE9, 63 PE10, 64 PE11, 65 PE12, 66 PE13, 67 PE14, 68 PE15, 77 PD8, 78 PD9, 79 PD10, 80 PD11, 81 PD12, 82 PD13, 85 PD14, 86 PD15, 87 PG2, 88 PG3, 89 PG4, 90 PG5, 91 PG6, 92 PG7, 93 PG8, 114 PD0, 115 PD1, 116 PD2, 117 PD3, 118 PD4, 119 PD5, 122 PD6, 123 PD7, 124 PG9, 125 PG10, 126 PG11, 127 PG12, 128 PG13, 129 PG14, 132 PG15, 141 PE0
part C pins: 6 VBAT, 16 VSS, 17 VDD, 30 VDD, 31 VSSA, 32 VREFP, 33 VDDA, 38 VSS, 39 VDD, 51 VSS, 52 VDD, 61 VSS, 62 VDD, 70 VCAP, 71 VSS, 72 VDD, 83 VSS, 84 VDD, 94 VSS, 95 VDD, 106 VDDUSB, 107 VSS, 108 VDD, 120 VSS, 121 VDD2, 130 VSS, 131 VDD, 142 VCAP, 143 VSS, 144 VDD

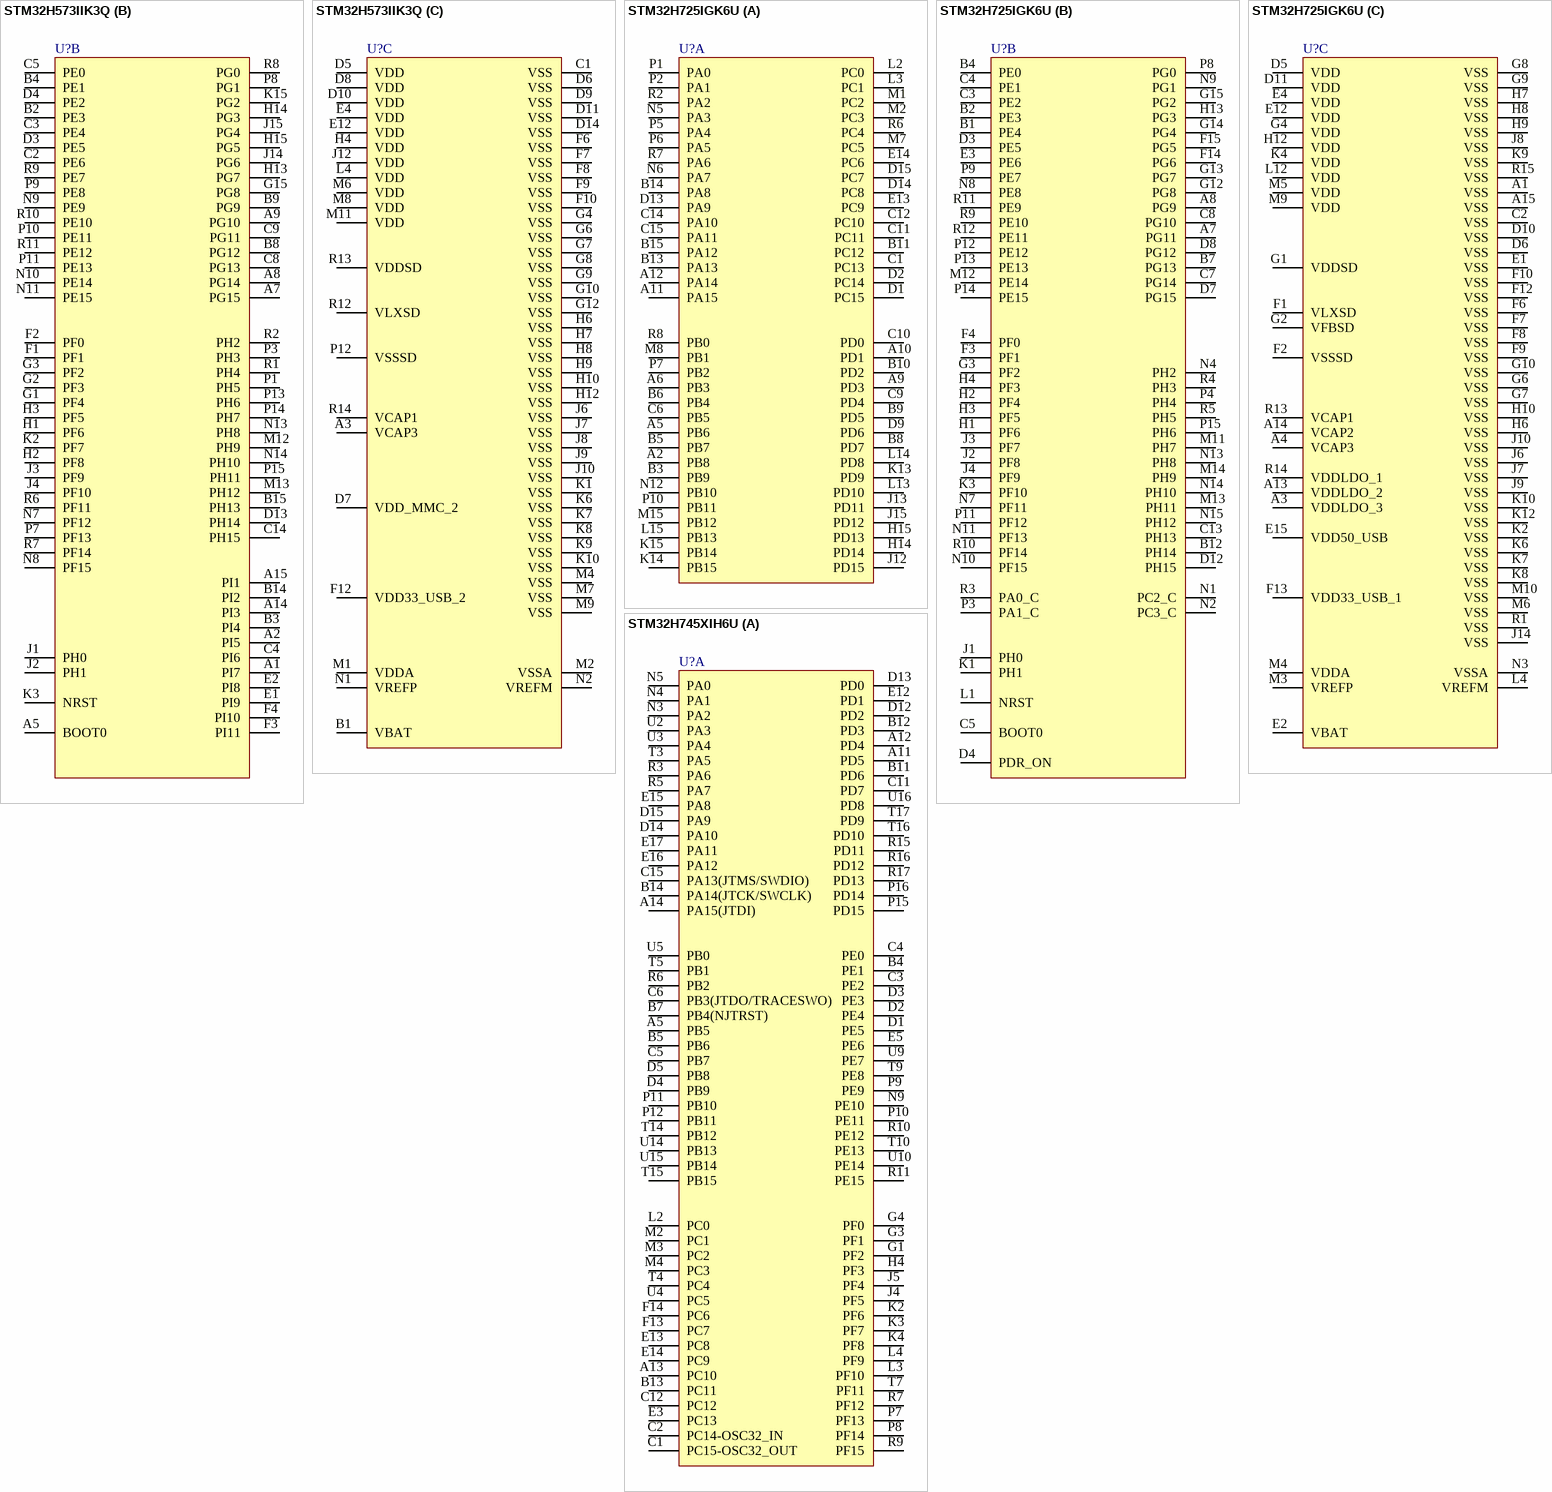
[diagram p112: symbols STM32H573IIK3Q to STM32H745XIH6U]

## STM32H573IIK3Q
designator U?
part A pins: A4 PB9, A6 PB5, A10 PD7, A11 PD5, A12 PD3, A13 PD1, B5 PB8, B6 PB6, B7 PB3, B10 PD6, B11 PD4, B12 PD0, B13 PA14, C6 PB7, C7 PB4, C10 PD2, C11 PC12, C12 PC11, C13 PA15, C15 PA12, D1 PC15, D2 PC14, D12 PC10, D15 PA11, E3 PC13, E13 PA13, E14 PA10, E15 PA9, F13 PC9, F14 PC8, F15 PA8, G13 PC7, G14 PC6, J13 PD15, K4 PC2, K12 PD10, K13 PD14, K14 PD12, L1 PC0, L2 PC1, L3 PA1, L12 PB12, L13 PD9, L14 PD11, L15 PD13, M3 PA2, M5 PA4, M10 PB10, M14 PB15, M15 PD8, N3 PC3, N4 PC4, N5 PA3, N6 PB1, N12 PB11, N15 PB14, P2 PA0, P4 PC5, P5 PA6, P6 PB2, R3 PA5, R4 PA7, R5 PB0, R15 PB13
part B pins: A1 PI7, A2 PI5, A5 BOOT0, A7 PG15, A8 PG14, A9 PG10, A14 PI3, A15 PI1, B2 PE3, B3 PI4, B4 PE1, B8 PG12, B9 PG9, B14 PI2, B15 PH13, C2 PE6, C3 PE4, C4 PI6, C5 PE0, C8 PG13, C9 PG11, C14 PH15, D3 PE5, D4 PE2, D13 PH14, E1 PI9, E2 PI8, F1 PF1, F2 PF0, F3 PI11, F4 PI10, G1 PF4, G2 PF3, G3 PF2, G15 PG8, H1 PF6, H2 PF8, H3 PF5, H13 PG7, H14 PG3, H15 PG5, J1 PH0, J2 PH1, J3 PF9, J4 PF10, J14 PG6, J15 PG4, K2 PF7, K3 NRST, K15 PG2, M12 PH9, M13 PH12, N7 PF12, N8 PF15, N9 PE9, N10 PE14, N11 PE15, N13 PH8, N14 PH10, P1 PH5, P3 PH3, P7 PF13, P8 PG1, P9 PE8, P10 PE11, P11 PE13, P13 PH6, P14 PH7, P15 PH11, R1 PH4, R2 PH2, R6 PF11, R7 PF14, R8 PG0, R9 PE7, R10 PE10, R11 PE12
part C pins: A3 VCAP3, B1 VBAT, C1 VSS, D5 VDD, D6 VSS, D7 VDD_MMC_2, D8 VDD, D9 VSS, D10 VDD, D11 VSS, D14 VSS, E4 VDD, E12 VDD, F6 VSS, F7 VSS, F8 VSS, F9 VSS, F10 VSS, F12 VDD33_USB_2, G4 VSS, G6 VSS, G7 VSS, G8 VSS, G9 VSS, G10 VSS, G12 VSS, H4 VDD, H6 VSS, H7 VSS, H8 VSS, H9 VSS, H10 VSS, H12 VSS, J6 VSS, J7 VSS, J8 VSS, J9 VSS, J10 VSS, J12 VDD, K1 VSS, K6 VSS, K7 VSS, K8 VSS, K9 VSS, K10 VSS, L4 VDD, M1 VDDA, M2 VSSA, M4 VSS, M6 VDD, M7 VSS, M8 VDD, M9 VSS, M11 VDD, N1 VREFP, N2 VREFM, P12 VSSSD, R12 VLXSD, R13 VDDSD, R14 VCAP1

## STM32H725IGK6U
designator U?
part A pins: A2 PB8, A5 PB6, A6 PB3, A9 PD3, A10 PD1, A11 PA15, A12 PA14, B3 PB9, B5 PB7, B6 PB4, B8 PD7, B9 PD5, B10 PD2, B11 PC12, B13 PA13, B14 PA8, B15 PA12, C1 PC13, C6 PB5, C9 PD4, C10 PD0, C11 PC11, C12 PC10, C14 PA10, C15 PA11, D1 PC15, D2 PC14, D9 PD6, D13 PA9, D14 PC8, D15 PC7, E13 PC9, E14 PC6, H14 PD14, H15 PD13, J12 PD15, J13 PD11, J15 PD12, K13 PD9, K14 PB15, K15 PB14, L2 PC0, L3 PC1, L13 PD10, L14 PD8, L15 PB13, M1 PC2, M2 PC3, M7 PC5, M8 PB1, M15 PB12, N5 PA3, N6 PA7, N12 PB10, P1 PA0, P2 PA1, P5 PA4, P6 PA5, P7 PB2, P10 PB11, R2 PA2, R6 PC4, R7 PA6, R8 PB0
part B pins: A7 PG11, A8 PG9, B1 PE4, B2 PE3, B4 PE0, B7 PG13, B12 PH14, C3 PE2, C4 PE1, C5 BOOT0, C7 PG14, C8 PG10, C13 PH13, D3 PE5, D4 PDR_ON, D7 PG15, D8 PG12, D12 PH15, E3 PE6, F3 PF1, F4 PF0, F14 PG6, F15 PG5, G3 PF2, G12 PG8, G13 PG7, G14 PG4, G15 PG2, H1 PF6, H2 PF4, H3 PF5, H4 PF3, H13 PG3, J1 PH0, J2 PF8, J3 PF7, J4 PF9, K1 PH1, K3 PF10, L1 NRST, M11 PH7, M12 PE14, M13 PH11, M14 PH9, N1 PC2_C, N2 PC3_C, N4 PH2, N7 PF11, N8 PE8, N9 PG1, N10 PF15, N11 PF13, N13 PH8, N14 PH10, N15 PH12, P3 PA1_C, P4 PH4, P8 PG0, P9 PE7, P11 PF12, P12 PE12, P13 PE13, P14 PE15, P15 PH6, R3 PA0_C, R4 PH3, R5 PH5, R9 PE10, R10 PF14, R11 PE9, R12 PE11
part C pins: A1 VSS, A3 VDDLDO_3, A4 VCAP3, A13 VDDLDO_2, A14 VCAP2, A15 VSS, C2 VSS, D5 VDD, D6 VSS, D10 VSS, D11 VDD, E1 VSS, E2 VBAT, E4 VDD, E12 VDD, E15 VDD50_USB, F1 VLXSD, F2 VSSSD, F6 VSS, F7 VSS, F8 VSS, F9 VSS, F10 VSS, F12 VSS, F13 VDD33_USB_1, G1 VDDSD, G2 VFBSD, G4 VDD, G6 VSS, G7 VSS, G8 VSS, G9 VSS, G10 VSS, H6 VSS, H7 VSS, H8 VSS, H9 VSS, H10 VSS, H12 VDD, J6 VSS, J7 VSS, J8 VSS, J9 VSS, J10 VSS, J14 VSS, K2 VSS, K4 VDD, K6 VSS, K7 VSS, K8 VSS, K9 VSS, K10 VSS, K12 VSS, L4 VREFM, L12 VDD, M3 VREFP, M4 VDDA, M5 VDD, M6 VSS, M9 VDD, M10 VSS, N3 VSSA, R1 VSS, R13 VCAP1, R14 VDDLDO_1, R15 VSS

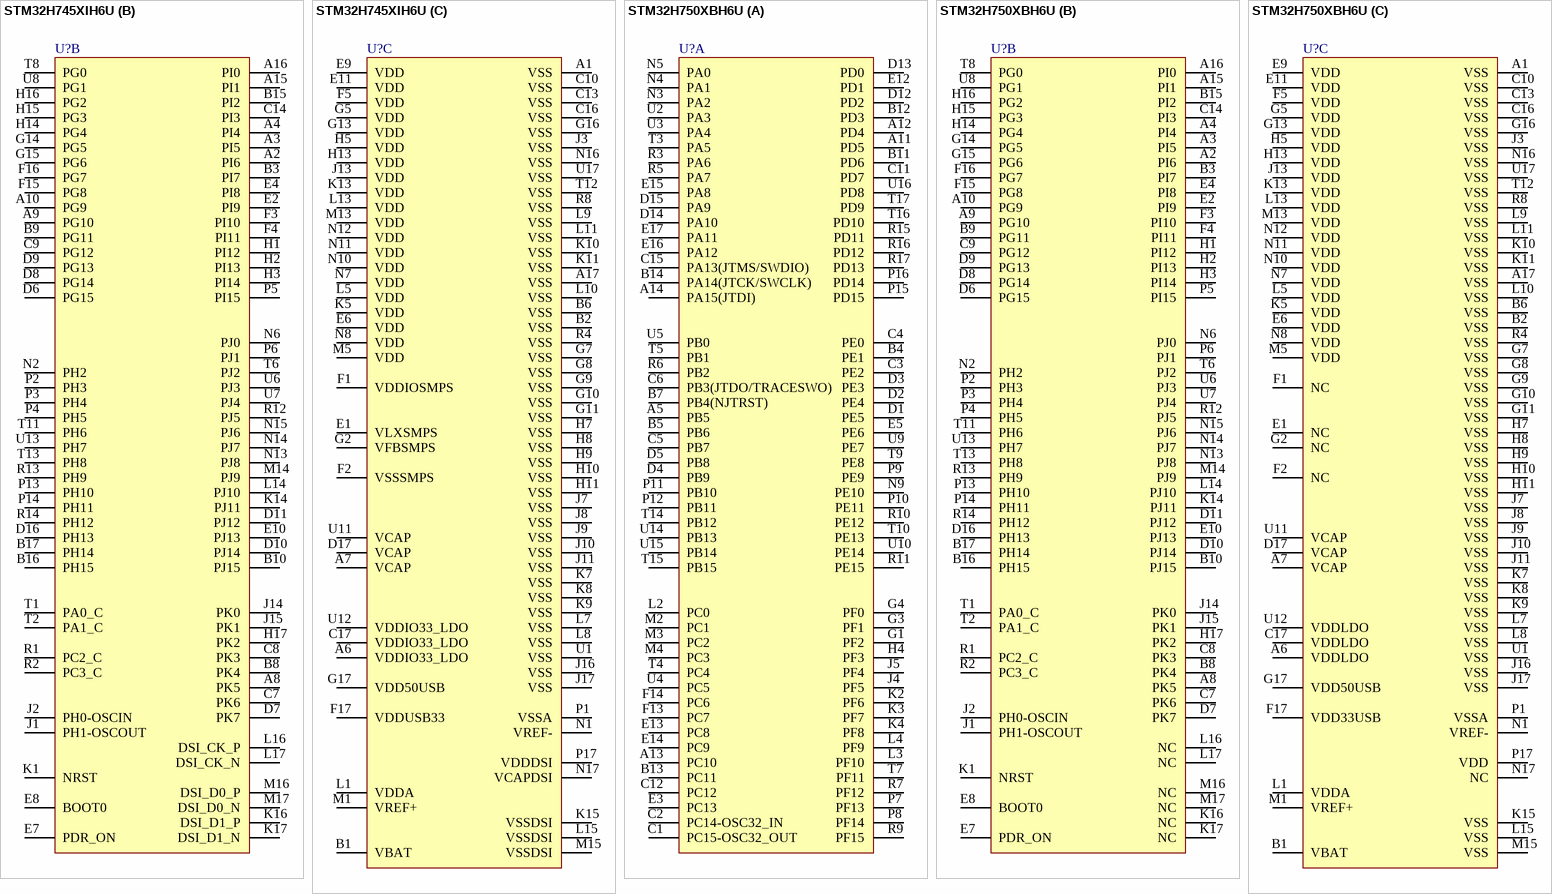
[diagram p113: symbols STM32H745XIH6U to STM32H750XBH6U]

## STM32H745XIH6U
designator U?
part A pins: A5 PB5, A11 PD5, A12 PD4, A13 PC10, A14 PA15(JTDI), B4 PE1, B5 PB6, B7 PB4(NJTRST), B11 PD6, B12 PD3, B13 PC11, B14 PA14(JTCK/SWCLK), C1 PC15-OSC32_OUT, C2 PC14-OSC32_IN, C3 PE2, C4 PE0, C5 PB7, C6 PB3(JTDO/TRACESWO), C11 PD7, C12 PC12, C15 PA13(JTMS/SWDIO), D1 PE5, D2 PE4, D3 PE3, D4 PB9, D5 PB8, D12 PD2, D13 PD0, D14 PA10, D15 PA9, E3 PC13, E5 PE6, E12 PD1, E13 PC8, E14 PC9, E15 PA8, E16 PA12, E17 PA11, F13 PC7, F14 PC6, G1 PF2, G3 PF1, G4 PF0, H4 PF3, J4 PF5, J5 PF4, K2 PF6, K3 PF7, K4 PF8, L2 PC0, L3 PF10, L4 PF9, M2 PC1, M3 PC2, M4 PC3, N3 PA2, N4 PA1, N5 PA0, N9 PE10, P7 PF13, P8 PF14, P9 PE9, P10 PE11, P11 PB10, P12 PB11, P15 PD15, P16 PD14, R3 PA6, R5 PA7, R6 PB2, R7 PF12, R9 PF15, R10 PE12, R11 PE15, R15 PD11, R16 PD12, R17 PD13, T3 PA5, T4 PC4, T5 PB1, T7 PF11, T9 PE8, T10 PE13, T14 PB12, T15 PB15, T16 PD10, T17 PD9, U2 PA3, U3 PA4, U4 PC5, U5 PB0, U9 PE7, U10 PE14, U14 PB13, U15 PB14, U16 PD8
part B pins: A2 PI6, A3 PI5, A4 PI4, A8 PK5, A9 PG10, A10 PG9, A15 PI1, A16 PI0, B3 PI7, B8 PK4, B9 PG11, B10 PJ15, B15 PI2, B16 PH15, B17 PH14, C7 PK6, C8 PK3, C9 PG12, C14 PI3, D6 PG15, D7 PK7, D8 PG14, D9 PG13, D10 PJ14, D11 PJ12, D16 PH13, E2 PI9, E4 PI8, E7 PDR_ON, E8 BOOT0, E10 PJ13, F3 PI10, F4 PI11, F15 PG8, F16 PG7, G14 PG5, G15 PG6, H1 PI12, H2 PI13, H3 PI14, H14 PG4, H15 PG3, H16 PG2, H17 PK2, J1 PH1-OSCOUT, J2 PH0-OSCIN, J14 PK0, J15 PK1, K1 NRST, K14 PJ11, K16 DSI_D1_P, K17 DSI_D1_N, L14 PJ10, L16 DSI_CK_P, L17 DSI_CK_N, M14 PJ9, M16 DSI_D0_P, M17 DSI_D0_N, N2 PH2, N6 PJ0, N13 PJ8, N14 PJ7, N15 PJ6, P2 PH3, P3 PH4, P4 PH5, P5 PI15, P6 PJ1, P13 PH10, P14 PH11, R1 PC2_C, R2 PC3_C, R12 PJ5, R13 PH9, R14 PH12, T1 PA0_C, T2 PA1_C, T6 PJ2, T8 PG0, T11 PH6, T13 PH8, U6 PJ3, U7 PJ4, U8 PG1, U13 PH7
part C pins: A1 VSS, A6 VDDIO33_LDO, A7 VCAP, A17 VSS, B1 VBAT, B2 VSS, B6 VSS, C10 VSS, C13 VSS, C16 VSS, C17 VDDIO33_LDO, D17 VCAP, E1 VLXSMPS, E6 VDD, E9 VDD, E11 VDD, F1 VDDIOSMPS, F2 VSSSMPS, F5 VDD, F17 VDDUSB33, G2 VFBSMPS, G5 VDD, G7 VSS, G8 VSS, G9 VSS, G10 VSS, G11 VSS, G13 VDD, G16 VSS, G17 VDD50USB, H5 VDD, H7 VSS, H8 VSS, H9 VSS, H10 VSS, H11 VSS, H13 VDD, J3 VSS, J7 VSS, J8 VSS, J9 VSS, J10 VSS, J11 VSS, J13 VDD, J16 VSS, J17 VSS, K5 VDD, K7 VSS, K8 VSS, K9 VSS, K10 VSS, K11 VSS, K13 VDD, K15 VSSDSI, L1 VDDA, L5 VDD, L7 VSS, L8 VSS, L9 VSS, L10 VSS, L11 VSS, L13 VDD, L15 VSSDSI, M1 VREF+, M5 VDD, M13 VDD, M15 VSSDSI, N1 VREF-, N7 VDD, N8 VDD, N10 VDD, N11 VDD, N12 VDD, N16 VSS, N17 VCAPDSI, P1 VSSA, P17 VDDDSI, R4 VSS, R8 VSS, T12 VSS, U1 VSS, U11 VCAP, U12 VDDIO33_LDO, U17 VSS

## STM32H750XBH6U
designator U?
part A pins: A5 PB5, A11 PD5, A12 PD4, A13 PC10, A14 PA15(JTDI), B4 PE1, B5 PB6, B7 PB4(NJTRST), B11 PD6, B12 PD3, B13 PC11, B14 PA14(JTCK/SWCLK), C1 PC15-OSC32_OUT, C2 PC14-OSC32_IN, C3 PE2, C4 PE0, C5 PB7, C6 PB3(JTDO/TRACESWO), C11 PD7, C12 PC12, C15 PA13(JTMS/SWDIO), D1 PE5, D2 PE4, D3 PE3, D4 PB9, D5 PB8, D12 PD2, D13 PD0, D14 PA10, D15 PA9, E3 PC13, E5 PE6, E12 PD1, E13 PC8, E14 PC9, E15 PA8, E16 PA12, E17 PA11, F13 PC7, F14 PC6, G1 PF2, G3 PF1, G4 PF0, H4 PF3, J4 PF5, J5 PF4, K2 PF6, K3 PF7, K4 PF8, L2 PC0, L3 PF10, L4 PF9, M2 PC1, M3 PC2, M4 PC3, N3 PA2, N4 PA1, N5 PA0, N9 PE10, P7 PF13, P8 PF14, P9 PE9, P10 PE11, P11 PB10, P12 PB11, P15 PD15, P16 PD14, R3 PA6, R5 PA7, R6 PB2, R7 PF12, R9 PF15, R10 PE12, R11 PE15, R15 PD11, R16 PD12, R17 PD13, T3 PA5, T4 PC4, T5 PB1, T7 PF11, T9 PE8, T10 PE13, T14 PB12, T15 PB15, T16 PD10, T17 PD9, U2 PA3, U3 PA4, U4 PC5, U5 PB0, U9 PE7, U10 PE14, U14 PB13, U15 PB14, U16 PD8
part B pins: A2 PI6, A3 PI5, A4 PI4, A8 PK5, A9 PG10, A10 PG9, A15 PI1, A16 PI0, B3 PI7, B8 PK4, B9 PG11, B10 PJ15, B15 PI2, B16 PH15, B17 PH14, C7 PK6, C8 PK3, C9 PG12, C14 PI3, D6 PG15, D7 PK7, D8 PG14, D9 PG13, D10 PJ14, D11 PJ12, D16 PH13, E2 PI9, E4 PI8, E7 PDR_ON, E8 BOOT0, E10 PJ13, F3 PI10, F4 PI11, F15 PG8, F16 PG7, G14 PG5, G15 PG6, H1 PI12, H2 PI13, H3 PI14, H14 PG4, H15 PG3, H16 PG2, H17 PK2, J1 PH1-OSCOUT, J2 PH0-OSCIN, J14 PK0, J15 PK1, K1 NRST, K14 PJ11, K16 NC, K17 NC, L14 PJ10, L16 NC, L17 NC, M14 PJ9, M16 NC, M17 NC, N2 PH2, N6 PJ0, N13 PJ8, N14 PJ7, N15 PJ6, P2 PH3, P3 PH4, P4 PH5, P5 PI15, P6 PJ1, P13 PH10, P14 PH11, R1 PC2_C, R2 PC3_C, R12 PJ5, R13 PH9, R14 PH12, T1 PA0_C, T2 PA1_C, T6 PJ2, T8 PG0, T11 PH6, T13 PH8, U6 PJ3, U7 PJ4, U8 PG1, U13 PH7
part C pins: A1 VSS, A6 VDDLDO, A7 VCAP, A17 VSS, B1 VBAT, B2 VSS, B6 VSS, C10 VSS, C13 VSS, C16 VSS, C17 VDDLDO, D17 VCAP, E1 NC, E6 VDD, E9 VDD, E11 VDD, F1 NC, F2 NC, F5 VDD, F17 VDD33USB, G2 NC, G5 VDD, G7 VSS, G8 VSS, G9 VSS, G10 VSS, G11 VSS, G13 VDD, G16 VSS, G17 VDD50USB, H5 VDD, H7 VSS, H8 VSS, H9 VSS, H10 VSS, H11 VSS, H13 VDD, J3 VSS, J7 VSS, J8 VSS, J9 VSS, J10 VSS, J11 VSS, J13 VDD, J16 VSS, J17 VSS, K5 VDD, K7 VSS, K8 VSS, K9 VSS, K10 VSS, K11 VSS, K13 VDD, K15 VSS, L1 VDDA, L5 VDD, L7 VSS, L8 VSS, L9 VSS, L10 VSS, L11 VSS, L13 VDD, L15 VSS, M1 VREF+, M5 VDD, M13 VDD, M15 VSS, N1 VREF-, N7 VDD, N8 VDD, N10 VDD, N11 VDD, N12 VDD, N16 VSS, N17 NC, P1 VSSA, P17 VDD, R4 VSS, R8 VSS, T12 VSS, U1 VSS, U11 VCAP, U12 VDDLDO, U17 VSS

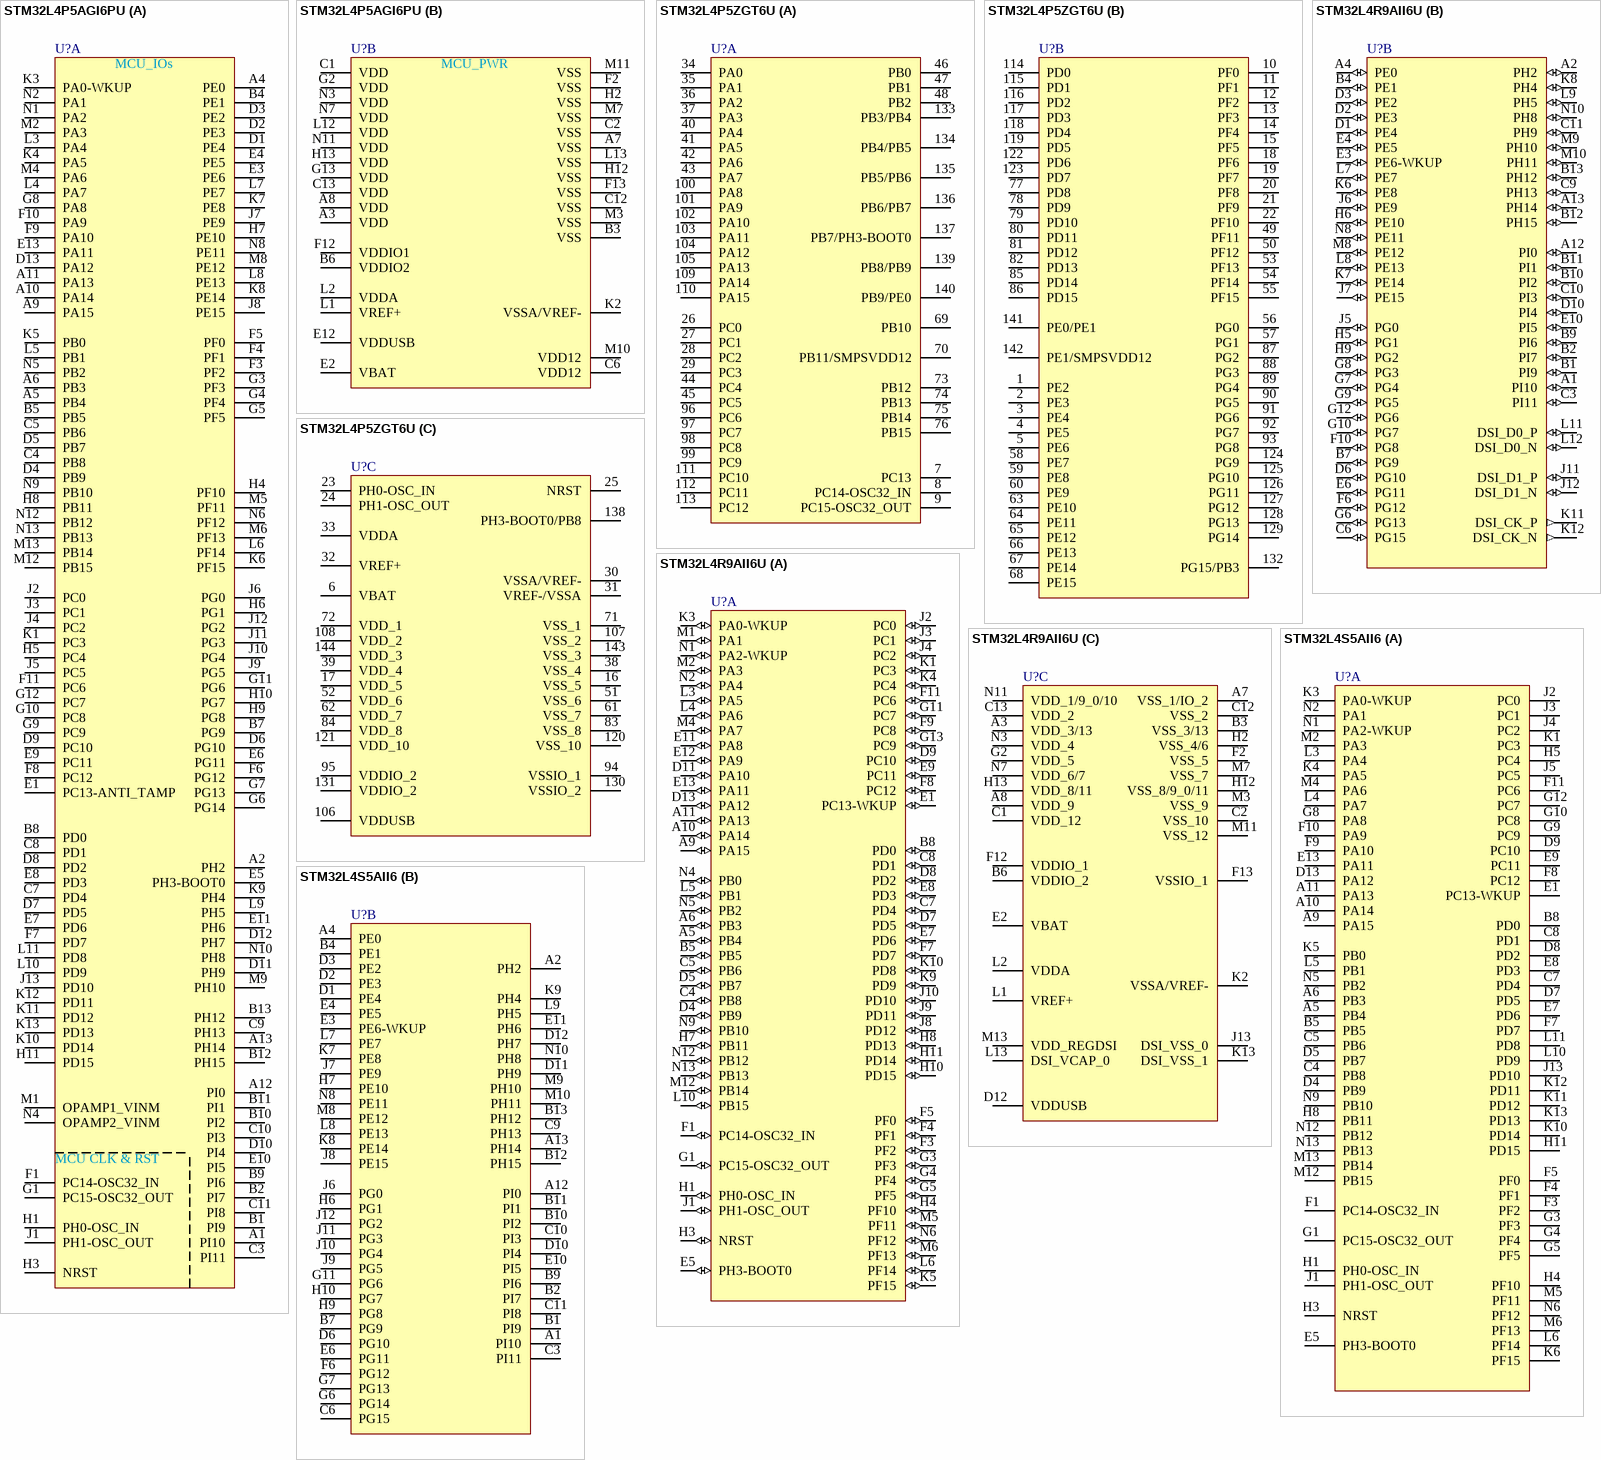
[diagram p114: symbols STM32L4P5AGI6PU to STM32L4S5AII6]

## STM32L4P5AGI6PU
designator U?
part A pins: A1 PI10, A2 PH2, A4 PE0, A5 PB4, A6 PB3, A9 PA15, A10 PA14, A11 PA13, A12 PI0, A13 PH14, B1 PI9, B2 PI7, B4 PE1, B5 PB5, B7 PG9, B8 PD0, B9 PI6, B10 PI2, B11 PI1, B12 PH15, B13 PH12, C3 PI11, C4 PB8, C5 PB6, C7 PD4, C8 PD1, C9 PH13, C10 PI3, C11 PI8, D1 PE4, D2 PE3, D3 PE2, D4 PB9, D5 PB7, D6 PG10, D7 PD5, D8 PD2, D9 PC10, D10 PI4, D11 PH9, D12 PH7, D13 PA12, E1 PC13-ANTI_TAMP, E3 PE6, E4 PE5, E5 PH3-BOOT0, E6 PG11, E7 PD6, E8 PD3, E9 PC11, E10 PI5, E11 PH6, E13 PA11, F1 PC14-OSC32_IN, F3 PF2, F4 PF1, F5 PF0, F6 PG12, F7 PD7, F8 PC12, F9 PA10, F10 PA9, F11 PC6, G1 PC15-OSC32_OUT, G3 PF3, G4 PF4, G5 PF5, G6 PG14, G7 PG13, G8 PA8, G9 PC9, G10 PC8, G11 PG6, G12 PC7, H1 PH0-OSC_IN, H3 NRST, H4 PF10, H5 PC4, H6 PG1, H7 PE10, H8 PB11, H9 PG8, H10 PG7, H11 PD15, J1 PH1-OSC_OUT, J2 PC0, J3 PC1, J4 PC2, J5 PC5, J6 PG0, J7 PE9, J8 PE15, J9 PG5, J10 PG4, J11 PG3, J12 PG2, J13 PD10, K1 PC3, K3 PA0-WKUP, K4 PA5, K5 PB0, K6 PF15, K7 PE8, K8 PE14, K9 PH4, K10 PD14, K11 PD12, K12 PD11, K13 PD13, L3 PA4, L4 PA7, L5 PB1, L6 PF14, L7 PE7, L8 PE13, L9 PH5, L10 PD9, L11 PD8, M1 OPAMP1_VINM, M2 PA3, M4 PA6, M5 PF11, M6 PF13, M8 PE12, M9 PH10, M12 PB15, M13 PB14, N1 PA2, N2 PA1, N4 OPAMP2_VINM, N5 PB2, N6 PF12, N8 PE11, N9 PB10, N10 PH8, N12 PB12, N13 PB13
part B pins: A3 VDD, A7 VSS, A8 VDD, B3 VSS, B6 VDDIO2, C1 VDD, C2 VSS, C6 VDD12, C12 VSS, C13 VDD, E2 VBAT, E12 VDDUSB, F2 VSS, F12 VDDIO1, F13 VSS, G2 VDD, G13 VDD, H2 VSS, H12 VSS, H13 VDD, K2 VSSA/VREF-, L1 VREF+, L2 VDDA, L12 VDD, L13 VSS, M3 VSS, M7 VSS, M10 VDD12, M11 VSS, N3 VDD, N7 VDD, N11 VDD

## STM32L4P5ZGT6U
designator U?
part A pins: 7 PC13, 8 PC14-OSC32_IN, 9 PC15-OSC32_OUT, 26 PC0, 27 PC1, 28 PC2, 29 PC3, 34 PA0, 35 PA1, 36 PA2, 37 PA3, 40 PA4, 41 PA5, 42 PA6, 43 PA7, 44 PC4, 45 PC5, 46 PB0, 47 PB1, 48 PB2, 69 PB10, 70 PB11/SMPSVDD12, 73 PB12, 74 PB13, 75 PB14, 76 PB15, 96 PC6, 97 PC7, 98 PC8, 99 PC9, 100 PA8, 101 PA9, 102 PA10, 103 PA11, 104 PA12, 105 PA13, 109 PA14, 110 PA15, 111 PC10, 112 PC11, 113 PC12, 133 PB3/PB4, 134 PB4/PB5, 135 PB5/PB6, 136 PB6/PB7, 137 PB7/PH3-BOOT0, 139 PB8/PB9, 140 PB9/PE0
part B pins: 1 PE2, 2 PE3, 3 PE4, 4 PE5, 5 PE6, 10 PF0, 11 PF1, 12 PF2, 13 PF3, 14 PF4, 15 PF5, 18 PF6, 19 PF7, 20 PF8, 21 PF9, 22 PF10, 49 PF11, 50 PF12, 53 PF13, 54 PF14, 55 PF15, 56 PG0, 57 PG1, 58 PE7, 59 PE8, 60 PE9, 63 PE10, 64 PE11, 65 PE12, 66 PE13, 67 PE14, 68 PE15, 77 PD8, 78 PD9, 79 PD10, 80 PD11, 81 PD12, 82 PD13, 85 PD14, 86 PD15, 87 PG2, 88 PG3, 89 PG4, 90 PG5, 91 PG6, 92 PG7, 93 PG8, 114 PD0, 115 PD1, 116 PD2, 117 PD3, 118 PD4, 119 PD5, 122 PD6, 123 PD7, 124 PG9, 125 PG10, 126 PG11, 127 PG12, 128 PG13, 129 PG14, 132 PG15/PB3, 141 PE0/PE1, 142 PE1/SMPSVDD12
part C pins: 6 VBAT, 16 VSS_5, 17 VDD_5, 23 PH0-OSC_IN, 24 PH1-OSC_OUT, 25 NRST, 30 VSSA/VREF-, 31 VREF-/VSSA, 32 VREF+, 33 VDDA, 38 VSS_4, 39 VDD_4, 51 VSS_6, 52 VDD_6, 61 VSS_7, 62 VDD_7, 71 VSS_1, 72 VDD_1, 83 VSS_8, 84 VDD_8, 94 VSSIO_1, 95 VDDIO_2, 106 VDDUSB, 107 VSS_2, 108 VDD_2, 120 VSS_10, 121 VDD_10, 130 VSSIO_2, 131 VDDIO_2, 138 PH3-BOOT0/PB8, 143 VSS_3, 144 VDD_3

## STM32L4R9AII6U
designator U?
part A pins: A5 PB4 (io), A6 PB3 (io), A9 PA15 (io), A10 PA14 (io), A11 PA13 (io), B5 PB5 (io), B8 PD0 (io), C4 PB8 (io), C5 PB6 (io), C7 PD4 (io), C8 PD1 (io), D4 PB9 (io), D5 PB7 (io), D7 PD5 (io), D8 PD2 (io), D9 PC10 (io), D11 PA10 (io), D13 PA12 (io), E1 PC13-WKUP (io), E5 PH3-BOOT0 (io), E7 PD6 (io), E8 PD3 (io), E9 PC11 (io), E11 PA8 (io), E12 PA9 (io), E13 PA11 (io), F1 PC14-OSC32_IN (io), F3 PF2 (io), F4 PF1 (io), F5 PF0 (io), F7 PD7 (io), F8 PC12 (io), F9 PC8 (io), F11 PC6 (io), G1 PC15-OSC32_OUT (io), G3 PF3 (io), G4 PF4 (io), G5 PF5 (io), G11 PC7 (io), G13 PC9 (io), H1 PH0-OSC_IN (io), H3 NRST (io), H4 PF10 (io), H7 PB11 (io), H8 PD13 (io), H10 PD15 (io), H11 PD14 (io), J1 PH1-OSC_OUT (io), J2 PC0 (io), J3 PC1 (io), J4 PC2 (io), J8 PD12 (io), J9 PD11 (io), J10 PD10 (io), K1 PC3 (io), K3 PA0-WKUP (io), K4 PC4 (io), K5 PF15 (io), K9 PD9 (io), K10 PD8 (io), L3 PA5 (io), L4 PA6 (io), L5 PB1 (io), L6 PF14 (io), L10 PB15 (io), M1 PA1 (io), M2 PA3 (io), M4 PA7 (io), M5 PF11 (io), M6 PF13 (io), M12 PB14 (io), N1 PA2-WKUP (io), N2 PA4 (io), N4 PB0 (io), N5 PB2 (io), N6 PF12 (io), N9 PB10 (io), N12 PB12 (io), N13 PB13 (io)
part B pins: A1 PI10 (io), A2 PH2 (io), A4 PE0 (io), A12 PI0 (io), A13 PH14 (io), B1 PI9 (io), B2 PI7 (io), B4 PE1 (io), B7 PG9 (io), B9 PI6 (io), B10 PI2 (io), B11 PI1 (io), B12 PH15 (io), B13 PH12 (io), C3 PI11 (io), C6 PG15 (io), C9 PH13 (io), C10 PI3 (io), C11 PH9 (io), D1 PE4 (io), D2 PE3 (io), D3 PE2 (io), D6 PG10 (io), D10 PI4 (io), E3 PE6-WKUP (io), E4 PE5 (io), E6 PG11 (io), E10 PI5 (io), F6 PG12 (io), F10 PG8 (io), G6 PG13 (io), G7 PG4 (io), G8 PG3 (io), G9 PG5 (io), G10 PG7 (io), G12 PG6 (io), H5 PG1 (io), H6 PE10 (io), H9 PG2 (io), J5 PG0 (io), J6 PE9 (io), J7 PE15 (io), J11 DSI_D1_P (io), J12 DSI_D1_N (io), K6 PE8 (io), K7 PE14 (io), K8 PH4 (io), K11 DSI_CK_P (out), K12 DSI_CK_N (out), L7 PE7 (io), L8 PE13 (io), L9 PH5 (io), L11 DSI_D0_P (io), L12 DSI_D0_N (io), M8 PE12 (io), M9 PH10 (io), M10 PH11 (io), N8 PE11 (io), N10 PH8 (io)
part C pins: A3 VDD_3/13 (power), A7 VSS_1/IO_2 (power), A8 VDD_9 (power), B3 VSS_3/13 (power), B6 VDDIO_2 (power), C1 VDD_12 (power), C2 VSS_10 (power), C12 VSS_2 (power), C13 VDD_2 (power), D12 VDDUSB (power), E2 VBAT (power), F2 VSS_5 (power), F12 VDDIO_1 (power), F13 VSSIO_1 (power), G2 VDD_5 (power), H2 VSS_4/6 (power), H12 VSS_8/9_0/11 (power), H13 VDD_8/11 (power), J13 DSI_VSS_0 (power), K2 VSSA/VREF- (power), K13 DSI_VSS_1 (power), L1 VREF+ (power), L2 VDDA (power), L13 DSI_VCAP_0 (power), M3 VSS_9 (power), M7 VSS_7 (power), M11 VSS_12 (power), M13 VDD_REGDSI (power), N3 VDD_4 (power), N7 VDD_6/7 (power), N11 VDD_1/9_0/10 (power)

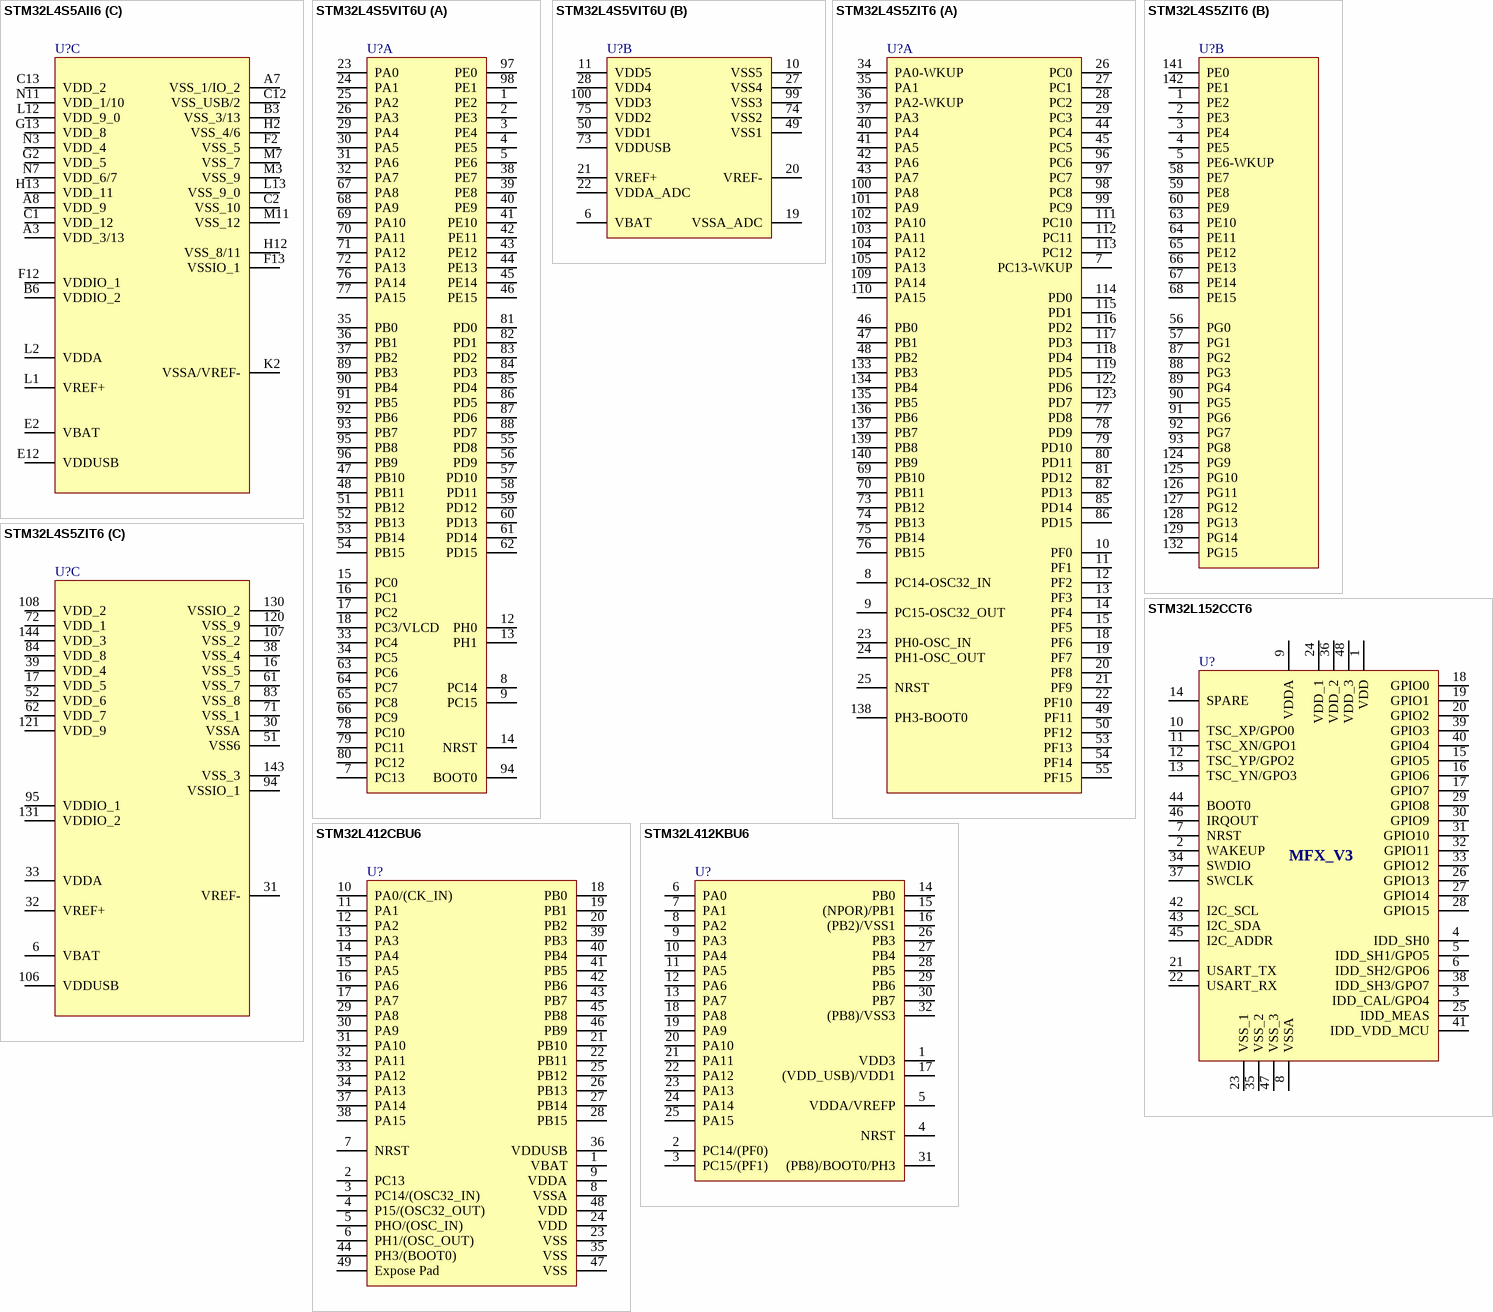
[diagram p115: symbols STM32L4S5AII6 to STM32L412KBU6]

## STM32L4S5AII6
designator U?
part A pins: A5 PB4, A6 PB3, A9 PA15, A10 PA14, A11 PA13, B5 PB5, B8 PD0, C4 PB8, C5 PB6, C7 PD4, C8 PD1, D4 PB9, D5 PB7, D7 PD5, D8 PD2, D9 PC10, D13 PA12, E1 PC13-WKUP, E5 PH3-BOOT0, E7 PD6, E8 PD3, E9 PC11, E13 PA11, F1 PC14-OSC32_IN, F3 PF2, F4 PF1, F5 PF0, F7 PD7, F8 PC12, F9 PA10, F10 PA9, F11 PC6, G1 PC15-OSC32_OUT, G3 PF3, G4 PF4, G5 PF5, G8 PA8, G9 PC9, G10 PC8, G12 PC7, H1 PH0-OSC_IN, H3 NRST, H4 PF10, H5 PC4, H8 PB11, H11 PD15, J1 PH1-OSC_OUT, J2 PC0, J3 PC1, J4 PC2, J5 PC5, J13 PD10, K1 PC3, K3 PA0-WKUP, K4 PA5, K5 PB0, K6 PF15, K10 PD14, K11 PD12, K12 PD11, K13 PD13, L3 PA4, L4 PA7, L5 PB1, L6 PF14, L10 PD9, L11 PD8, M2 PA3, M4 PA6, M5 PF11, M6 PF13, M12 PB15, M13 PB14, N1 PA2-WKUP, N2 PA1, N5 PB2, N6 PF12, N9 PB10, N12 PB12, N13 PB13
part B pins: A1 PI10, A2 PH2, A4 PE0, A12 PI0, A13 PH14, B1 PI9, B2 PI7, B4 PE1, B7 PG9, B9 PI6, B10 PI2, B11 PI1, B12 PH15, B13 PH12, C3 PI11, C6 PG15, C9 PH13, C10 PI3, C11 PI8, D1 PE4, D2 PE3, D3 PE2, D6 PG10, D10 PI4, D11 PH9, D12 PH7, E3 PE6-WKUP, E4 PE5, E6 PG11, E10 PI5, E11 PH6, F6 PG12, G6 PG14, G7 PG13, G11 PG6, H6 PG1, H7 PE10, H9 PG8, H10 PG7, J6 PG0, J7 PE9, J8 PE15, J9 PG5, J10 PG4, J11 PG3, J12 PG2, K7 PE8, K8 PE14, K9 PH4, L7 PE7, L8 PE13, L9 PH5, M8 PE12, M9 PH10, M10 PH11, N8 PE11, N10 PH8
part C pins: A3 VDD_3/13 (power), A7 VSS_1/IO_2 (power), A8 VDD_9 (power), B3 VSS_3/13 (power), B6 VDDIO_2 (power), C1 VDD_12 (power), C2 VSS_10 (power), C12 VSS_USB/2 (power), C13 VDD_2 (power), E2 VBAT (power), E12 VDDUSB (power), F2 VSS_5 (power), F12 VDDIO_1 (power), F13 VSSIO_1 (power), G2 VDD_5 (power), G13 VDD_8 (power), H2 VSS_4/6 (power), H12 VSS_8/11 (power), H13 VDD_11 (power), K2 VSSA/VREF- (power), L1 VREF+ (power), L2 VDDA (power), L12 VDD_9_0 (power), L13 VSS_9_0 (power), M3 VSS_9 (power), M7 VSS_7 (power), M11 VSS_12 (power), N3 VDD_4 (power), N7 VDD_6/7 (power), N11 VDD_1/10 (power)

## STM32L4S5VIT6U
designator U?
part A pins: 1 PE2, 2 PE3, 3 PE4, 4 PE5, 5 PE6, 7 PC13, 8 PC14, 9 PC15, 12 PH0, 13 PH1, 14 NRST, 15 PC0, 16 PC1, 17 PC2, 18 PC3/VLCD, 23 PA0, 24 PA1, 25 PA2, 26 PA3, 29 PA4, 30 PA5, 31 PA6, 32 PA7, 33 PC4, 34 PC5, 35 PB0, 36 PB1, 37 PB2, 38 PE7, 39 PE8, 40 PE9, 41 PE10, 42 PE11, 43 PE12, 44 PE13, 45 PE14, 46 PE15, 47 PB10, 48 PB11, 51 PB12, 52 PB13, 53 PB14, 54 PB15, 55 PD8, 56 PD9, 57 PD10, 58 PD11, 59 PD12, 60 PD13, 61 PD14, 62 PD15, 63 PC6, 64 PC7, 65 PC8, 66 PC9, 67 PA8, 68 PA9, 69 PA10, 70 PA11, 71 PA12, 72 PA13, 76 PA14, 77 PA15, 78 PC10, 79 PC11, 80 PC12, 81 PD0, 82 PD1, 83 PD2, 84 PD3, 85 PD4, 86 PD5, 87 PD6, 88 PD7, 89 PB3, 90 PB4, 91 PB5, 92 PB6, 93 PB7, 94 BOOT0, 95 PB8, 96 PB9, 97 PE0, 98 PE1
part B pins: 6 VBAT, 10 VSS5, 11 VDD5, 19 VSSA_ADC, 20 VREF-, 21 VREF+, 22 VDDA_ADC, 27 VSS4, 28 VDD4, 49 VSS1, 50 VDD1, 73 VDDUSB, 74 VSS2, 75 VDD2, 99 VSS3, 100 VDD3

## STM32L4S5ZIT6
designator U?
part A pins: 7 PC13-WKUP, 8 PC14-OSC32_IN, 9 PC15-OSC32_OUT, 10 PF0, 11 PF1, 12 PF2, 13 PF3, 14 PF4, 15 PF5, 18 PF6, 19 PF7, 20 PF8, 21 PF9, 22 PF10, 23 PH0-OSC_IN, 24 PH1-OSC_OUT, 25 NRST, 26 PC0, 27 PC1, 28 PC2, 29 PC3, 34 PA0-WKUP, 35 PA1, 36 PA2-WKUP, 37 PA3, 40 PA4, 41 PA5, 42 PA6, 43 PA7, 44 PC4, 45 PC5, 46 PB0, 47 PB1, 48 PB2, 49 PF11, 50 PF12, 53 PF13, 54 PF14, 55 PF15, 69 PB10, 70 PB11, 73 PB12, 74 PB13, 75 PB14, 76 PB15, 77 PD8, 78 PD9, 79 PD10, 80 PD11, 81 PD12, 82 PD13, 85 PD14, 86 PD15, 96 PC6, 97 PC7, 98 PC8, 99 PC9, 100 PA8, 101 PA9, 102 PA10, 103 PA11, 104 PA12, 105 PA13, 109 PA14, 110 PA15, 111 PC10, 112 PC11, 113 PC12, 114 PD0, 115 PD1, 116 PD2, 117 PD3, 118 PD4, 119 PD5, 122 PD6, 123 PD7, 133 PB3, 134 PB4, 135 PB5, 136 PB6, 137 PB7, 138 PH3-BOOT0, 139 PB8, 140 PB9
part B pins: 1 PE2, 2 PE3, 3 PE4, 4 PE5, 5 PE6-WKUP, 56 PG0, 57 PG1, 58 PE7, 59 PE8, 60 PE9, 63 PE10, 64 PE11, 65 PE12, 66 PE13, 67 PE14, 68 PE15, 87 PG2, 88 PG3, 89 PG4, 90 PG5, 91 PG6, 92 PG7, 93 PG8, 124 PG9, 125 PG10, 126 PG11, 127 PG12, 128 PG13, 129 PG14, 132 PG15, 141 PE0, 142 PE1
part C pins: 6 VBAT (power), 16 VSS_5 (power), 17 VDD_5 (power), 30 VSSA (power), 31 VREF- (power), 32 VREF+ (power), 33 VDDA (power), 38 VSS_4 (power), 39 VDD_4 (power), 51 VSS6 (power), 52 VDD_6 (power), 61 VSS_7 (power), 62 VDD_7 (power), 71 VSS_1 (power), 72 VDD_1 (power), 83 VSS_8 (power), 84 VDD_8 (power), 94 VSSIO_1 (power), 95 VDDIO_1 (power), 106 VDDUSB (power), 107 VSS_2 (power), 108 VDD_2 (power), 120 VSS_9 (power), 121 VDD_9 (power), 130 VSSIO_2 (power), 131 VDDIO_2 (power), 143 VSS_3 (power), 144 VDD_3 (power)

## STM32L152CCT6
designator U?
pins: 1 VDD, 2 WAKEUP, 3 IDD_CAL/GPO4, 4 IDD_SH0, 5 IDD_SH1/GPO5, 6 IDD_SH2/GPO6, 7 NRST, 8 VSSA, 9 VDDA, 10 TSC_XP/GPO0, 11 TSC_XN/GPO1, 12 TSC_YP/GPO2, 13 TSC_YN/GPO3, 14 SPARE, 15 GPIO5, 16 GPIO6, 17 GPIO7, 18 GPIO0, 19 GPIO1, 20 GPIO2, 21 USART_TX, 22 USART_RX, 23 VSS_1, 24 VDD_1, 25 IDD_MEAS, 26 GPIO13, 27 GPIO14, 28 GPIO15, 29 GPIO8, 30 GPIO9, 31 GPIO10, 32 GPIO11, 33 GPIO12, 34 SWDIO, 35 VSS_2, 36 VDD_2, 37 SWCLK, 38 IDD_SH3/GPO7, 39 GPIO3, 40 GPIO4, 41 IDD_VDD_MCU, 42 I2C_SCL, 43 I2C_SDA, 44 BOOT0, 45 I2C_ADDR, 46 IRQOUT, 47 VSS_3, 48 VDD_3

## STM32L412CBU6
designator U?
pins: 1 VBAT (power), 2 PC13, 3 PC14/(OSC32_IN), 4 P15/(OSC32_OUT), 5 PHO/(OSC_IN), 6 PH1/(OSC_OUT), 7 NRST, 8 VSSA, 9 VDDA (power), 10 PA0/(CK_IN), 11 PA1, 12 PA2, 13 PA3, 14 PA4, 15 PA5, 16 PA6, 17 PA7, 18 PB0, 19 PB1, 20 PB2, 21 PB10, 22 PB11, 23 VSS, 24 VDD, 25 PB12, 26 PB13, 27 PB14, 28 PB15, 29 PA8, 30 PA9, 31 PA10, 32 PA11, 33 PA12, 34 PA13, 35 VSS, 36 VDDUSB, 37 PA14, 38 PA15, 39 PB3, 40 PB4, 41 PB5, 42 PB6, 43 PB7, 44 PH3/(BOOT0), 45 PB8, 46 PB9, 47 VSS, 48 VDD, 49 Expose Pad

## STM32L412KBU6
designator U?
pins: 1 VDD3, 2 PC14/(PF0), 3 PC15/(PF1), 4 NRST, 5 VDDA/VREFP, 6 PA0, 7 PA1, 8 PA2, 9 PA3, 10 PA4, 11 PA5, 12 PA6, 13 PA7, 14 PB0, 15 (NPOR)/PB1, 16 (PB2)/VSS1, 17 (VDD_USB)/VDD1, 18 PA8, 19 PA9, 20 PA10, 21 PA11, 22 PA12, 23 PA13, 24 PA14, 25 PA15, 26 PB3, 27 PB4, 28 PB5, 29 PB6, 30 PB7, 31 (PB8)/BOOT0/PH3, 32 (PB8)/VSS3

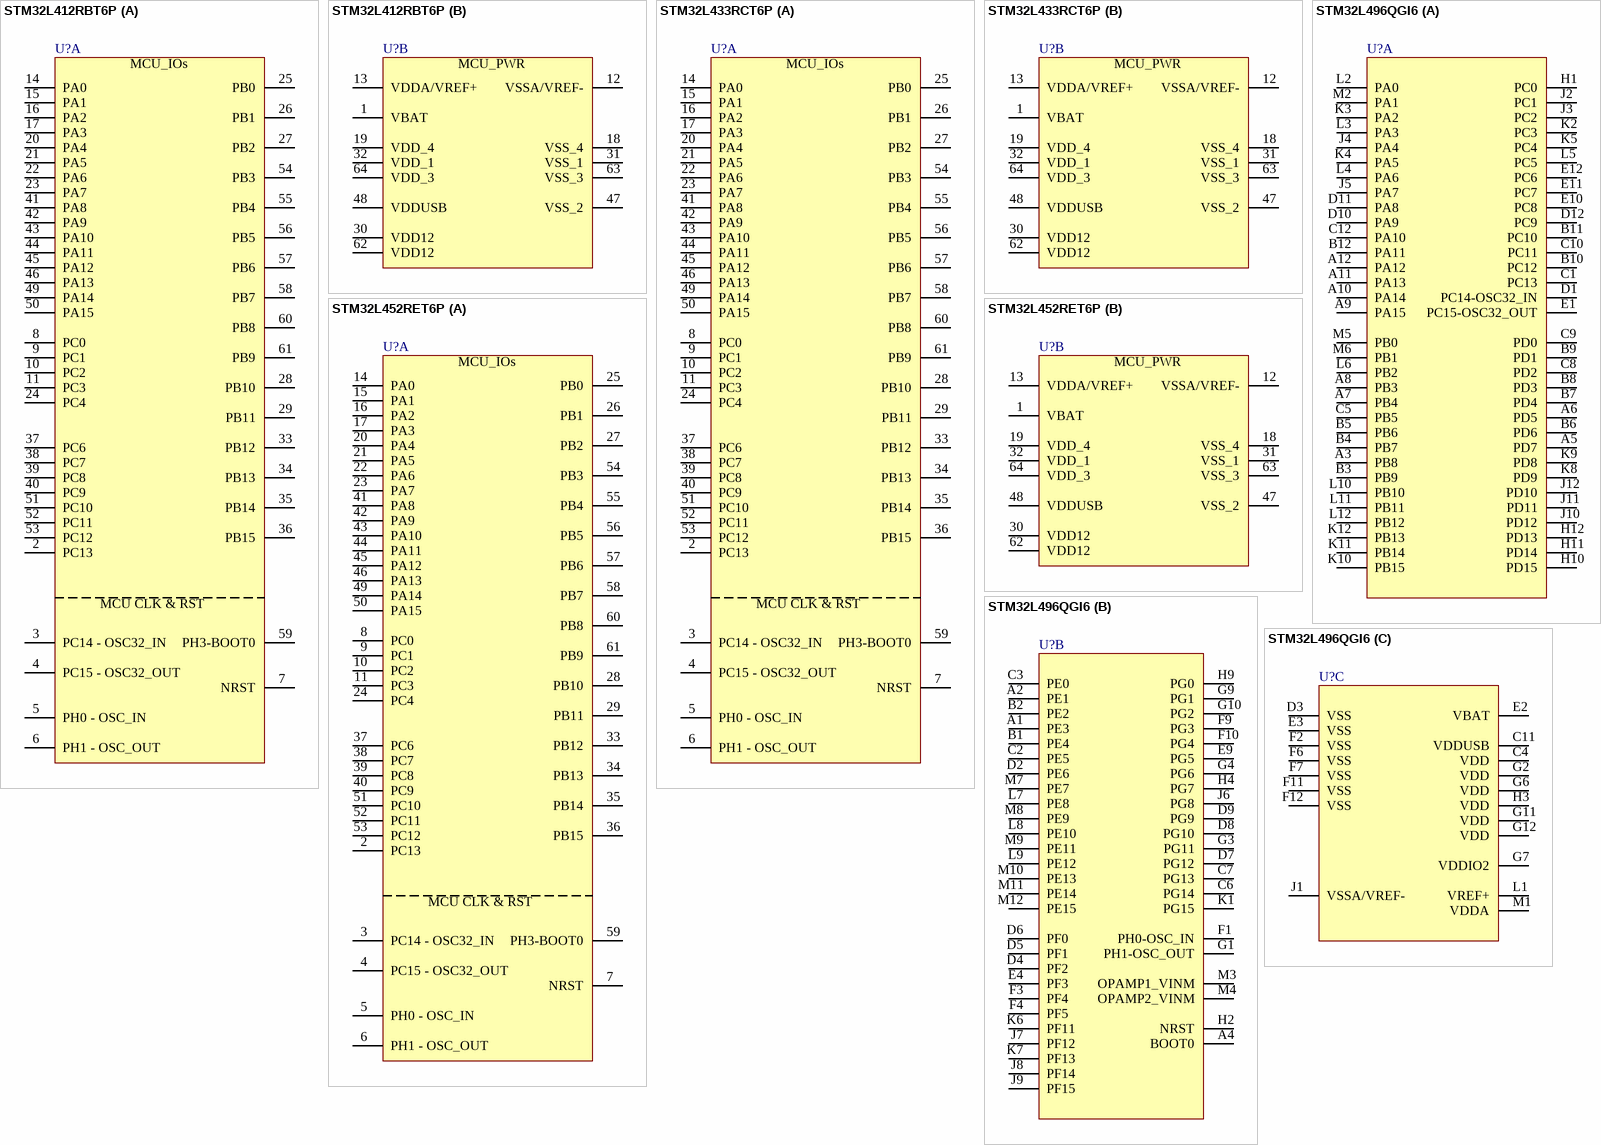
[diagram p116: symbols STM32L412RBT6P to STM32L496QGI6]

## STM32L412RBT6P
designator U?
part A pins: 2 PC13, 3 PC14 - OSC32_IN, 4 PC15 - OSC32_OUT, 5 PH0 - OSC_IN, 6 PH1 - OSC_OUT, 7 NRST, 8 PC0, 9 PC1, 10 PC2, 11 PC3, 14 PA0, 15 PA1, 16 PA2, 17 PA3, 20 PA4, 21 PA5, 22 PA6, 23 PA7, 24 PC4, 25 PB0, 26 PB1, 27 PB2, 28 PB10, 29 PB11, 33 PB12, 34 PB13, 35 PB14, 36 PB15, 37 PC6, 38 PC7, 39 PC8, 40 PC9, 41 PA8, 42 PA9, 43 PA10, 44 PA11, 45 PA12, 46 PA13, 49 PA14, 50 PA15, 51 PC10, 52 PC11, 53 PC12, 54 PB3, 55 PB4, 56 PB5, 57 PB6, 58 PB7, 59 PH3-BOOT0, 60 PB8, 61 PB9
part B pins: 1 VBAT, 12 VSSA/VREF-, 13 VDDA/VREF+, 18 VSS_4, 19 VDD_4, 30 VDD12, 31 VSS_1, 32 VDD_1, 47 VSS_2, 48 VDDUSB, 62 VDD12, 63 VSS_3, 64 VDD_3

## STM32L433RCT6P
designator U?
part A pins: 2 PC13, 3 PC14 - OSC32_IN, 4 PC15 - OSC32_OUT, 5 PH0 - OSC_IN, 6 PH1 - OSC_OUT, 7 NRST, 8 PC0, 9 PC1, 10 PC2, 11 PC3, 14 PA0, 15 PA1, 16 PA2, 17 PA3, 20 PA4, 21 PA5, 22 PA6, 23 PA7, 24 PC4, 25 PB0, 26 PB1, 27 PB2, 28 PB10, 29 PB11, 33 PB12, 34 PB13, 35 PB14, 36 PB15, 37 PC6, 38 PC7, 39 PC8, 40 PC9, 41 PA8, 42 PA9, 43 PA10, 44 PA11, 45 PA12, 46 PA13, 49 PA14, 50 PA15, 51 PC10, 52 PC11, 53 PC12, 54 PB3, 55 PB4, 56 PB5, 57 PB6, 58 PB7, 59 PH3-BOOT0, 60 PB8, 61 PB9
part B pins: 1 VBAT, 12 VSSA/VREF-, 13 VDDA/VREF+, 18 VSS_4, 19 VDD_4, 30 VDD12, 31 VSS_1, 32 VDD_1, 47 VSS_2, 48 VDDUSB, 62 VDD12, 63 VSS_3, 64 VDD_3

## STM32L452RET6P
designator U?
part A pins: 2 PC13, 3 PC14 - OSC32_IN, 4 PC15 - OSC32_OUT, 5 PH0 - OSC_IN, 6 PH1 - OSC_OUT, 7 NRST, 8 PC0, 9 PC1, 10 PC2, 11 PC3, 14 PA0, 15 PA1, 16 PA2, 17 PA3, 20 PA4, 21 PA5, 22 PA6, 23 PA7, 24 PC4, 25 PB0, 26 PB1, 27 PB2, 28 PB10, 29 PB11, 33 PB12, 34 PB13, 35 PB14, 36 PB15, 37 PC6, 38 PC7, 39 PC8, 40 PC9, 41 PA8, 42 PA9, 43 PA10, 44 PA11, 45 PA12, 46 PA13, 49 PA14, 50 PA15, 51 PC10, 52 PC11, 53 PC12, 54 PB3, 55 PB4, 56 PB5, 57 PB6, 58 PB7, 59 PH3-BOOT0, 60 PB8, 61 PB9
part B pins: 1 VBAT, 12 VSSA/VREF-, 13 VDDA/VREF+, 18 VSS_4, 19 VDD_4, 30 VDD12, 31 VSS_1, 32 VDD_1, 47 VSS_2, 48 VDDUSB, 62 VDD12, 63 VSS_3, 64 VDD_3

## STM32L496QGI6
designator U?
part A pins: A3 PB8, A5 PD7, A6 PD5, A7 PB4, A8 PB3, A9 PA15, A10 PA14, A11 PA13, A12 PA12, B3 PB9, B4 PB7, B5 PB6, B6 PD6, B7 PD4, B8 PD3, B9 PD1, B10 PC12, B11 PC10, B12 PA11, C1 PC13, C5 PB5, C8 PD2, C9 PD0, C10 PC11, C12 PA10, D1 PC14-OSC32_IN, D10 PA9, D11 PA8, D12 PC9, E1 PC15-OSC32_OUT, E10 PC8, E11 PC7, E12 PC6, H1 PC0, H10 PD15, H11 PD14, H12 PD13, J2 PC1, J3 PC2, J4 PA4, J5 PA7, J10 PD12, J11 PD11, J12 PD10, K2 PC3, K3 PA2, K4 PA5, K5 PC4, K8 PD9, K9 PD8, K10 PB15, K11 PB14, K12 PB13, L2 PA0, L3 PA3, L4 PA6, L5 PC5, L6 PB2, L10 PB10, L11 PB11, L12 PB12, M2 PA1, M5 PB0, M6 PB1
part B pins: A1 PE3, A2 PE1, A4 BOOT0, B1 PE4, B2 PE2, C2 PE5, C3 PE0, C6 PG14, C7 PG13, D2 PE6, D4 PF2, D5 PF1, D6 PF0, D7 PG12, D8 PG10, D9 PG9, E4 PF3, E9 PG5, F1 PH0-OSC_IN, F3 PF4, F4 PF5, F9 PG3, F10 PG4, G1 PH1-OSC_OUT, G3 PG11, G4 PG6, G9 PG1, G10 PG2, H2 NRST, H4 PG7, H9 PG0, J6 PG8, J7 PF12, J8 PF14, J9 PF15, K1 PG15, K6 PF11, K7 PF13, L7 PE8, L8 PE10, L9 PE12, M3 OPAMP1_VINM, M4 OPAMP2_VINM, M7 PE7, M8 PE9, M9 PE11, M10 PE13, M11 PE14, M12 PE15
part C pins: C4 VDD, C11 VDDUSB, D3 VSS, E2 VBAT, E3 VSS, F2 VSS, F6 VSS, F7 VSS, F11 VSS, F12 VSS, G2 VDD, G6 VDD, G7 VDDIO2, G11 VDD, G12 VDD, H3 VDD, J1 VSSA/VREF-, L1 VREF+, M1 VDDA

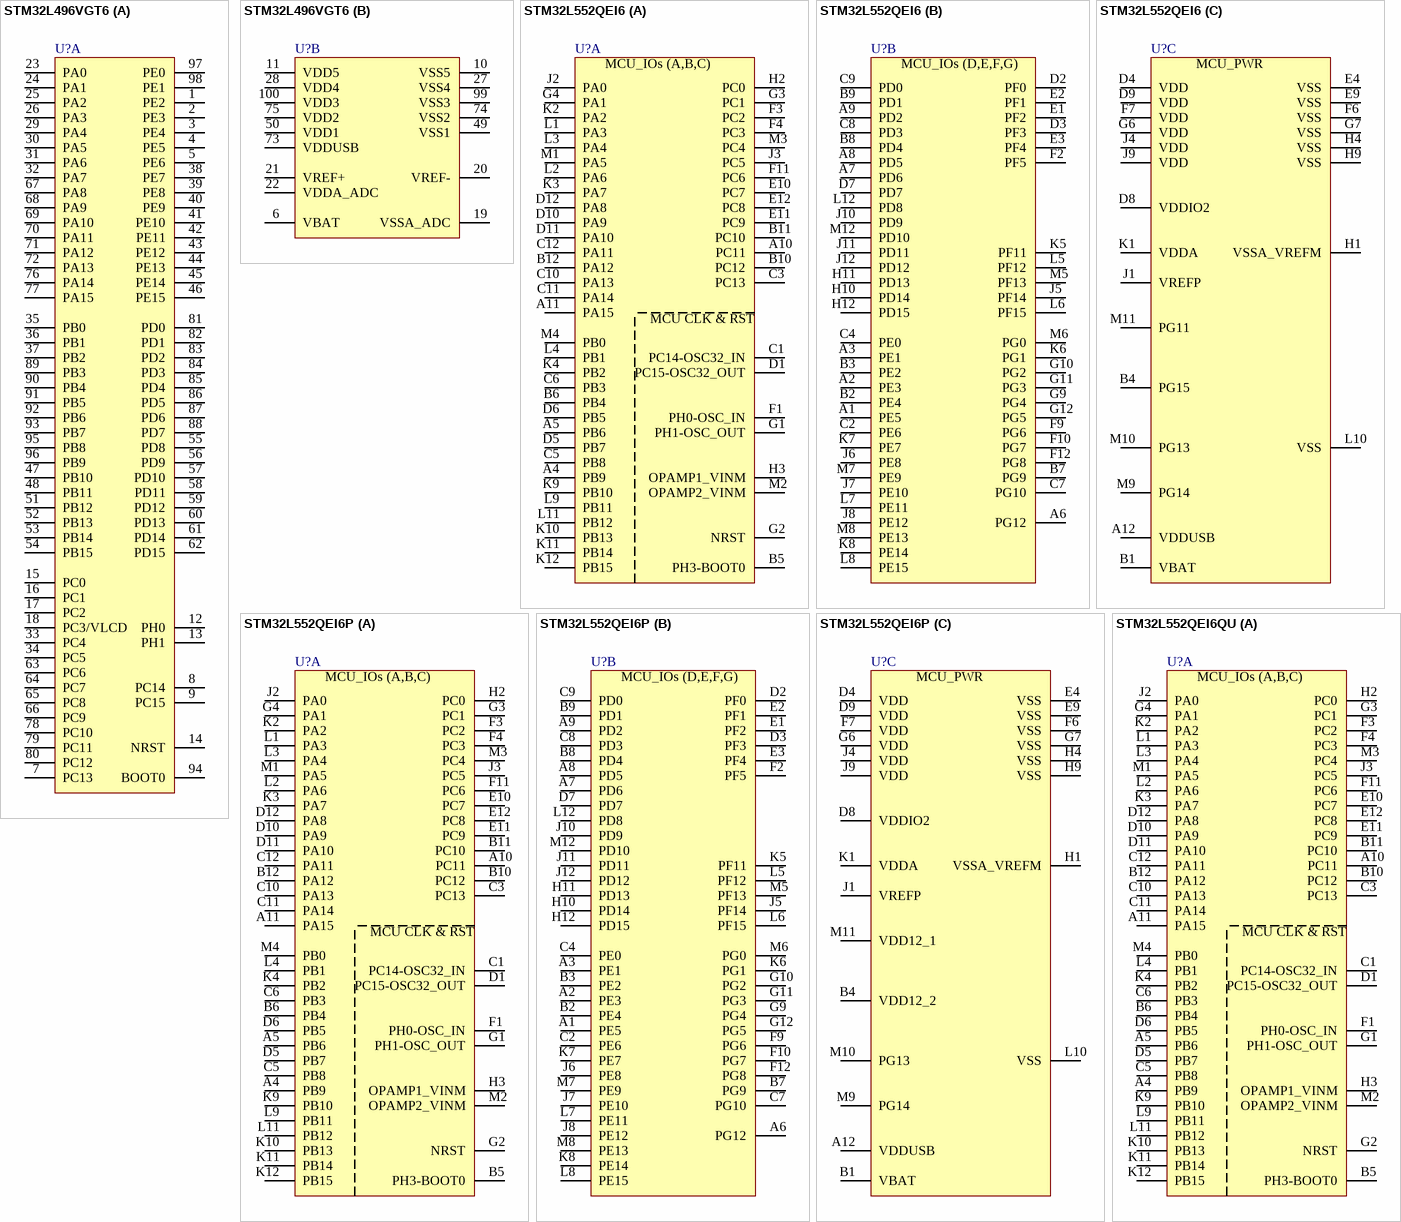
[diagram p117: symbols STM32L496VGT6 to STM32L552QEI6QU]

## STM32L496VGT6
designator U?
part A pins: 1 PE2, 2 PE3, 3 PE4, 4 PE5, 5 PE6, 7 PC13, 8 PC14, 9 PC15, 12 PH0, 13 PH1, 14 NRST, 15 PC0, 16 PC1, 17 PC2, 18 PC3/VLCD, 23 PA0, 24 PA1, 25 PA2, 26 PA3, 29 PA4, 30 PA5, 31 PA6, 32 PA7, 33 PC4, 34 PC5, 35 PB0, 36 PB1, 37 PB2, 38 PE7, 39 PE8, 40 PE9, 41 PE10, 42 PE11, 43 PE12, 44 PE13, 45 PE14, 46 PE15, 47 PB10, 48 PB11, 51 PB12, 52 PB13, 53 PB14, 54 PB15, 55 PD8, 56 PD9, 57 PD10, 58 PD11, 59 PD12, 60 PD13, 61 PD14, 62 PD15, 63 PC6, 64 PC7, 65 PC8, 66 PC9, 67 PA8, 68 PA9, 69 PA10, 70 PA11, 71 PA12, 72 PA13, 76 PA14, 77 PA15, 78 PC10, 79 PC11, 80 PC12, 81 PD0, 82 PD1, 83 PD2, 84 PD3, 85 PD4, 86 PD5, 87 PD6, 88 PD7, 89 PB3, 90 PB4, 91 PB5, 92 PB6, 93 PB7, 94 BOOT0, 95 PB8, 96 PB9, 97 PE0, 98 PE1
part B pins: 6 VBAT, 10 VSS5, 11 VDD5, 19 VSSA_ADC, 20 VREF-, 21 VREF+, 22 VDDA_ADC, 27 VSS4, 28 VDD4, 49 VSS1, 50 VDD1, 73 VDDUSB, 74 VSS2, 75 VDD2, 99 VSS3, 100 VDD3

## STM32L552QEI6
designator U?
part A pins: A4 PB9, A5 PB6, A10 PC11, A11 PA15, B5 PH3-BOOT0, B6 PB4, B10 PC12, B11 PC10, B12 PA12, C1 PC14-OSC32_IN, C3 PC13, C5 PB8, C6 PB3, C10 PA13, C11 PA14, C12 PA11, D1 PC15-OSC32_OUT, D5 PB7, D6 PB5, D10 PA9, D11 PA10, D12 PA8, E10 PC7, E11 PC9, E12 PC8, F1 PH0-OSC_IN, F3 PC2, F4 PC3, F11 PC6, G1 PH1-OSC_OUT, G2 NRST, G3 PC1, G4 PA1, H2 PC0, H3 OPAMP1_VINM, J2 PA0, J3 PC5, K2 PA2, K3 PA7, K4 PB2, K9 PB10, K10 PB13, K11 PB14, K12 PB15, L1 PA3, L2 PA6, L3 PA4, L4 PB1, L9 PB11, L11 PB12, M1 PA5, M2 OPAMP2_VINM, M3 PC4, M4 PB0
part B pins: A1 PE5, A2 PE3, A3 PE1, A6 PG12, A7 PD6, A8 PD5, A9 PD2, B2 PE4, B3 PE2, B7 PG9, B8 PD4, B9 PD1, C2 PE6, C4 PE0, C7 PG10, C8 PD3, C9 PD0, D2 PF0, D3 PF3, D7 PD7, E1 PF2, E2 PF1, E3 PF4, F2 PF5, F9 PG6, F10 PG7, F12 PG8, G9 PG4, G10 PG2, G11 PG3, G12 PG5, H10 PD14, H11 PD13, H12 PD15, J5 PF14, J6 PE8, J7 PE10, J8 PE12, J10 PD9, J11 PD11, J12 PD12, K5 PF11, K6 PG1, K7 PE7, K8 PE14, L5 PF12, L6 PF15, L7 PE11, L8 PE15, L12 PD8, M5 PF13, M6 PG0, M7 PE9, M8 PE13, M12 PD10
part C pins: A12 VDDUSB, B1 VBAT, B4 PG15, D4 VDD, D8 VDDIO2, D9 VDD, E4 VSS, E9 VSS, F6 VSS, F7 VDD, G6 VDD, G7 VSS, H1 VSSA_VREFM, H4 VSS, H9 VSS, J1 VREFP, J4 VDD, J9 VDD, K1 VDDA, L10 VSS, M9 PG14, M10 PG13, M11 PG11

## STM32L552QEI6P
designator U?
part A pins: A4 PB9, A5 PB6, A10 PC11, A11 PA15, B5 PH3-BOOT0, B6 PB4, B10 PC12, B11 PC10, B12 PA12, C1 PC14-OSC32_IN, C3 PC13, C5 PB8, C6 PB3, C10 PA13, C11 PA14, C12 PA11, D1 PC15-OSC32_OUT, D5 PB7, D6 PB5, D10 PA9, D11 PA10, D12 PA8, E10 PC7, E11 PC9, E12 PC8, F1 PH0-OSC_IN, F3 PC2, F4 PC3, F11 PC6, G1 PH1-OSC_OUT, G2 NRST, G3 PC1, G4 PA1, H2 PC0, H3 OPAMP1_VINM, J2 PA0, J3 PC5, K2 PA2, K3 PA7, K4 PB2, K9 PB10, K10 PB13, K11 PB14, K12 PB15, L1 PA3, L2 PA6, L3 PA4, L4 PB1, L9 PB11, L11 PB12, M1 PA5, M2 OPAMP2_VINM, M3 PC4, M4 PB0
part B pins: A1 PE5, A2 PE3, A3 PE1, A6 PG12, A7 PD6, A8 PD5, A9 PD2, B2 PE4, B3 PE2, B7 PG9, B8 PD4, B9 PD1, C2 PE6, C4 PE0, C7 PG10, C8 PD3, C9 PD0, D2 PF0, D3 PF3, D7 PD7, E1 PF2, E2 PF1, E3 PF4, F2 PF5, F9 PG6, F10 PG7, F12 PG8, G9 PG4, G10 PG2, G11 PG3, G12 PG5, H10 PD14, H11 PD13, H12 PD15, J5 PF14, J6 PE8, J7 PE10, J8 PE12, J10 PD9, J11 PD11, J12 PD12, K5 PF11, K6 PG1, K7 PE7, K8 PE14, L5 PF12, L6 PF15, L7 PE11, L8 PE15, L12 PD8, M5 PF13, M6 PG0, M7 PE9, M8 PE13, M12 PD10
part C pins: A12 VDDUSB, B1 VBAT, B4 VDD12_2, D4 VDD, D8 VDDIO2, D9 VDD, E4 VSS, E9 VSS, F6 VSS, F7 VDD, G6 VDD, G7 VSS, H1 VSSA_VREFM, H4 VSS, H9 VSS, J1 VREFP, J4 VDD, J9 VDD, K1 VDDA, L10 VSS, M9 PG14, M10 PG13, M11 VDD12_1

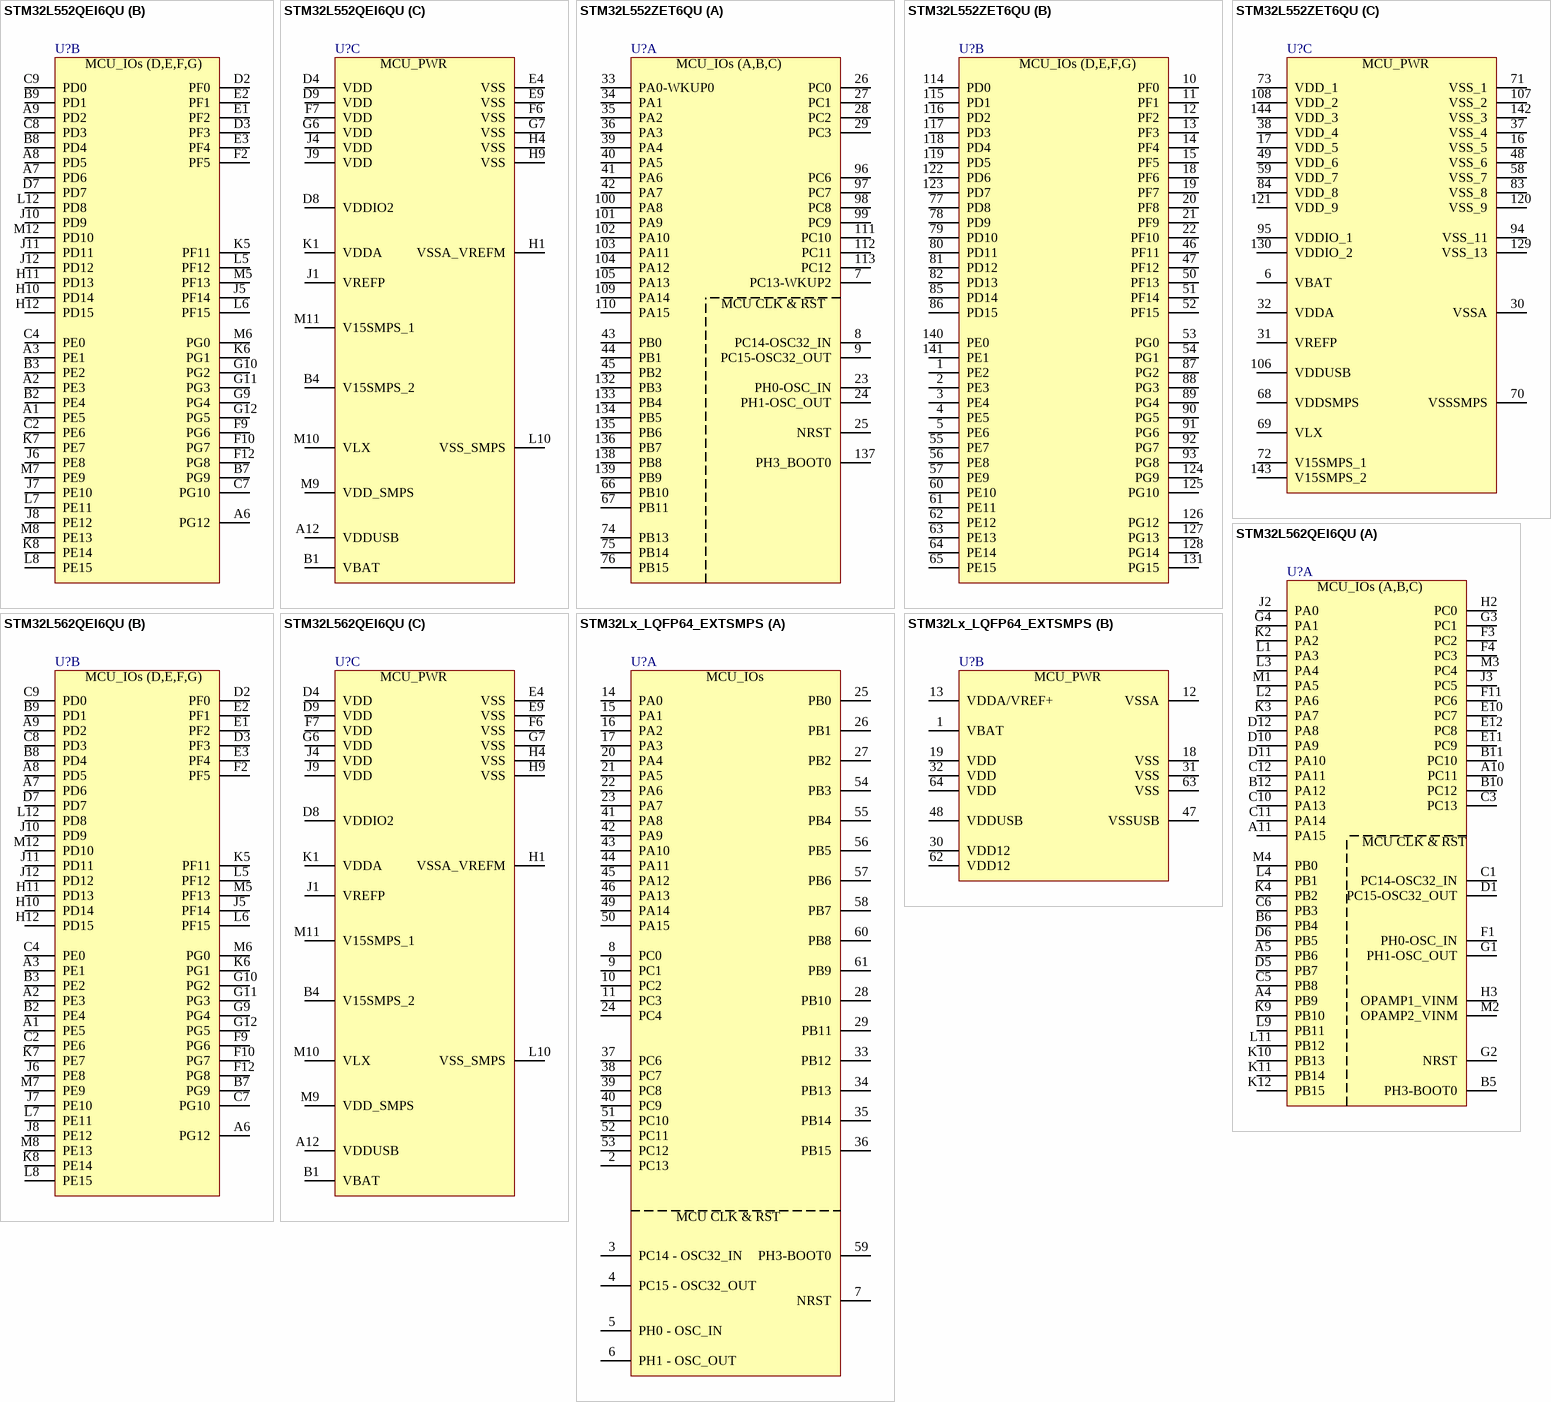
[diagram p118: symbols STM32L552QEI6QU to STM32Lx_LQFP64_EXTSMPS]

## STM32L552QEI6QU
designator U?
part A pins: A4 PB9, A5 PB6, A10 PC11, A11 PA15, B5 PH3-BOOT0, B6 PB4, B10 PC12, B11 PC10, B12 PA12, C1 PC14-OSC32_IN, C3 PC13, C5 PB8, C6 PB3, C10 PA13, C11 PA14, C12 PA11, D1 PC15-OSC32_OUT, D5 PB7, D6 PB5, D10 PA9, D11 PA10, D12 PA8, E10 PC7, E11 PC9, E12 PC8, F1 PH0-OSC_IN, F3 PC2, F4 PC3, F11 PC6, G1 PH1-OSC_OUT, G2 NRST, G3 PC1, G4 PA1, H2 PC0, H3 OPAMP1_VINM, J2 PA0, J3 PC5, K2 PA2, K3 PA7, K4 PB2, K9 PB10, K10 PB13, K11 PB14, K12 PB15, L1 PA3, L2 PA6, L3 PA4, L4 PB1, L9 PB11, L11 PB12, M1 PA5, M2 OPAMP2_VINM, M3 PC4, M4 PB0
part B pins: A1 PE5, A2 PE3, A3 PE1, A6 PG12, A7 PD6, A8 PD5, A9 PD2, B2 PE4, B3 PE2, B7 PG9, B8 PD4, B9 PD1, C2 PE6, C4 PE0, C7 PG10, C8 PD3, C9 PD0, D2 PF0, D3 PF3, D7 PD7, E1 PF2, E2 PF1, E3 PF4, F2 PF5, F9 PG6, F10 PG7, F12 PG8, G9 PG4, G10 PG2, G11 PG3, G12 PG5, H10 PD14, H11 PD13, H12 PD15, J5 PF14, J6 PE8, J7 PE10, J8 PE12, J10 PD9, J11 PD11, J12 PD12, K5 PF11, K6 PG1, K7 PE7, K8 PE14, L5 PF12, L6 PF15, L7 PE11, L8 PE15, L12 PD8, M5 PF13, M6 PG0, M7 PE9, M8 PE13, M12 PD10
part C pins: A12 VDDUSB, B1 VBAT, B4 V15SMPS_2, D4 VDD, D8 VDDIO2, D9 VDD, E4 VSS, E9 VSS, F6 VSS, F7 VDD, G6 VDD, G7 VSS, H1 VSSA_VREFM, H4 VSS, H9 VSS, J1 VREFP, J4 VDD, J9 VDD, K1 VDDA, L10 VSS_SMPS, M9 VDD_SMPS, M10 VLX, M11 V15SMPS_1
